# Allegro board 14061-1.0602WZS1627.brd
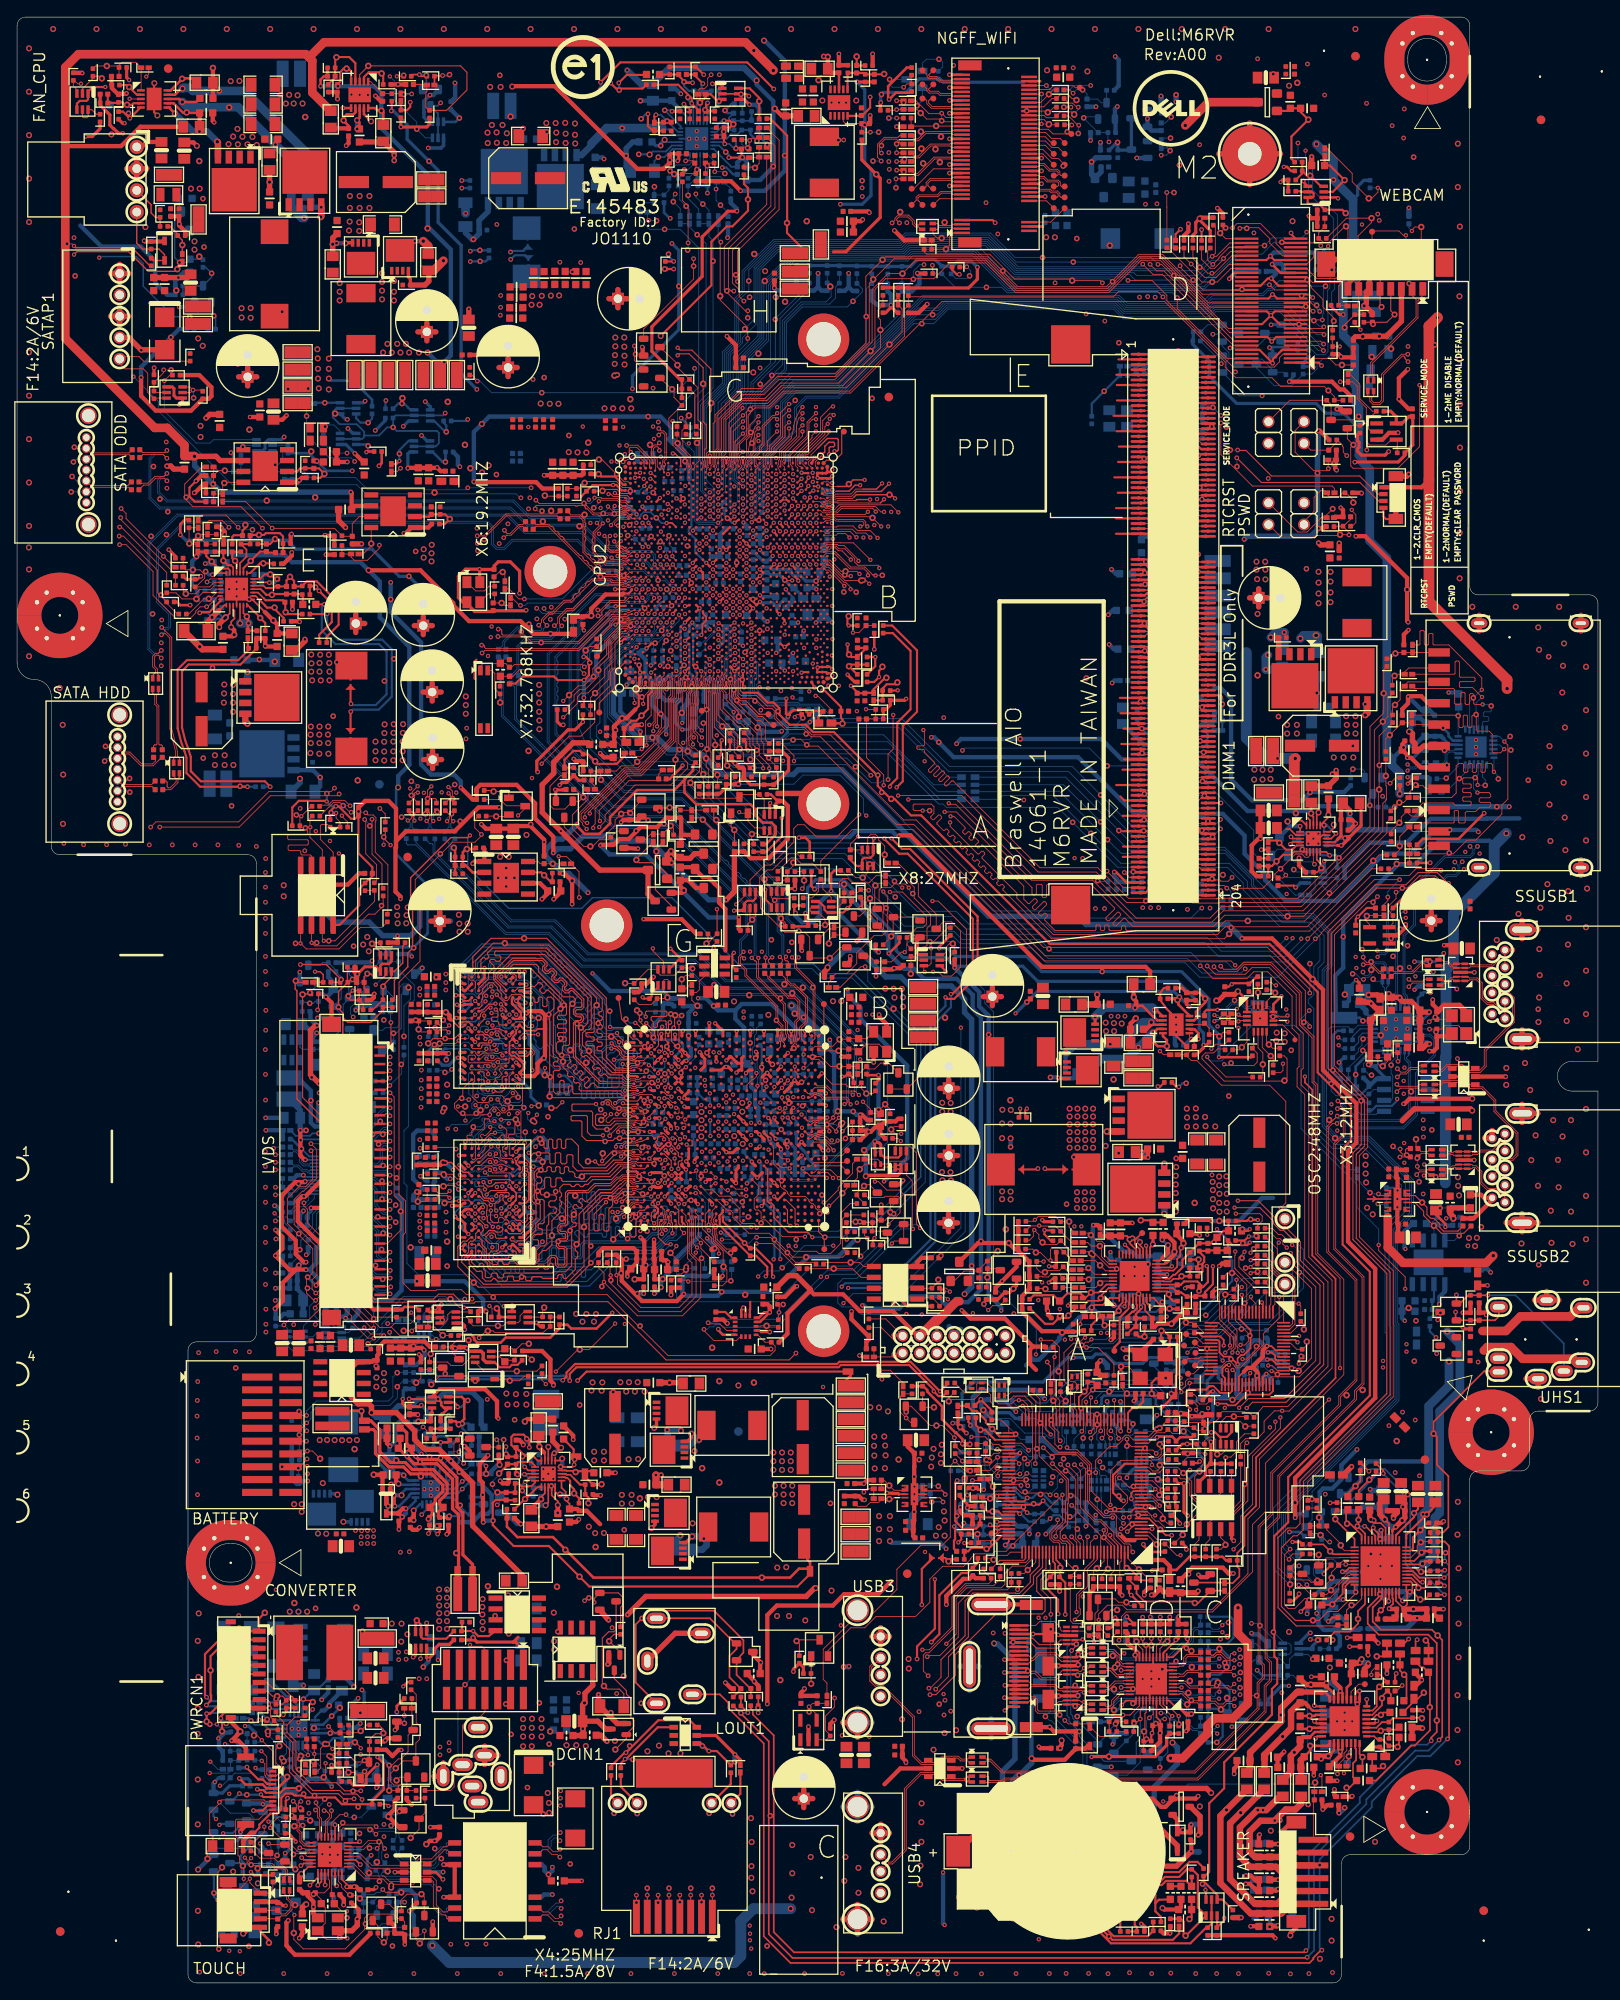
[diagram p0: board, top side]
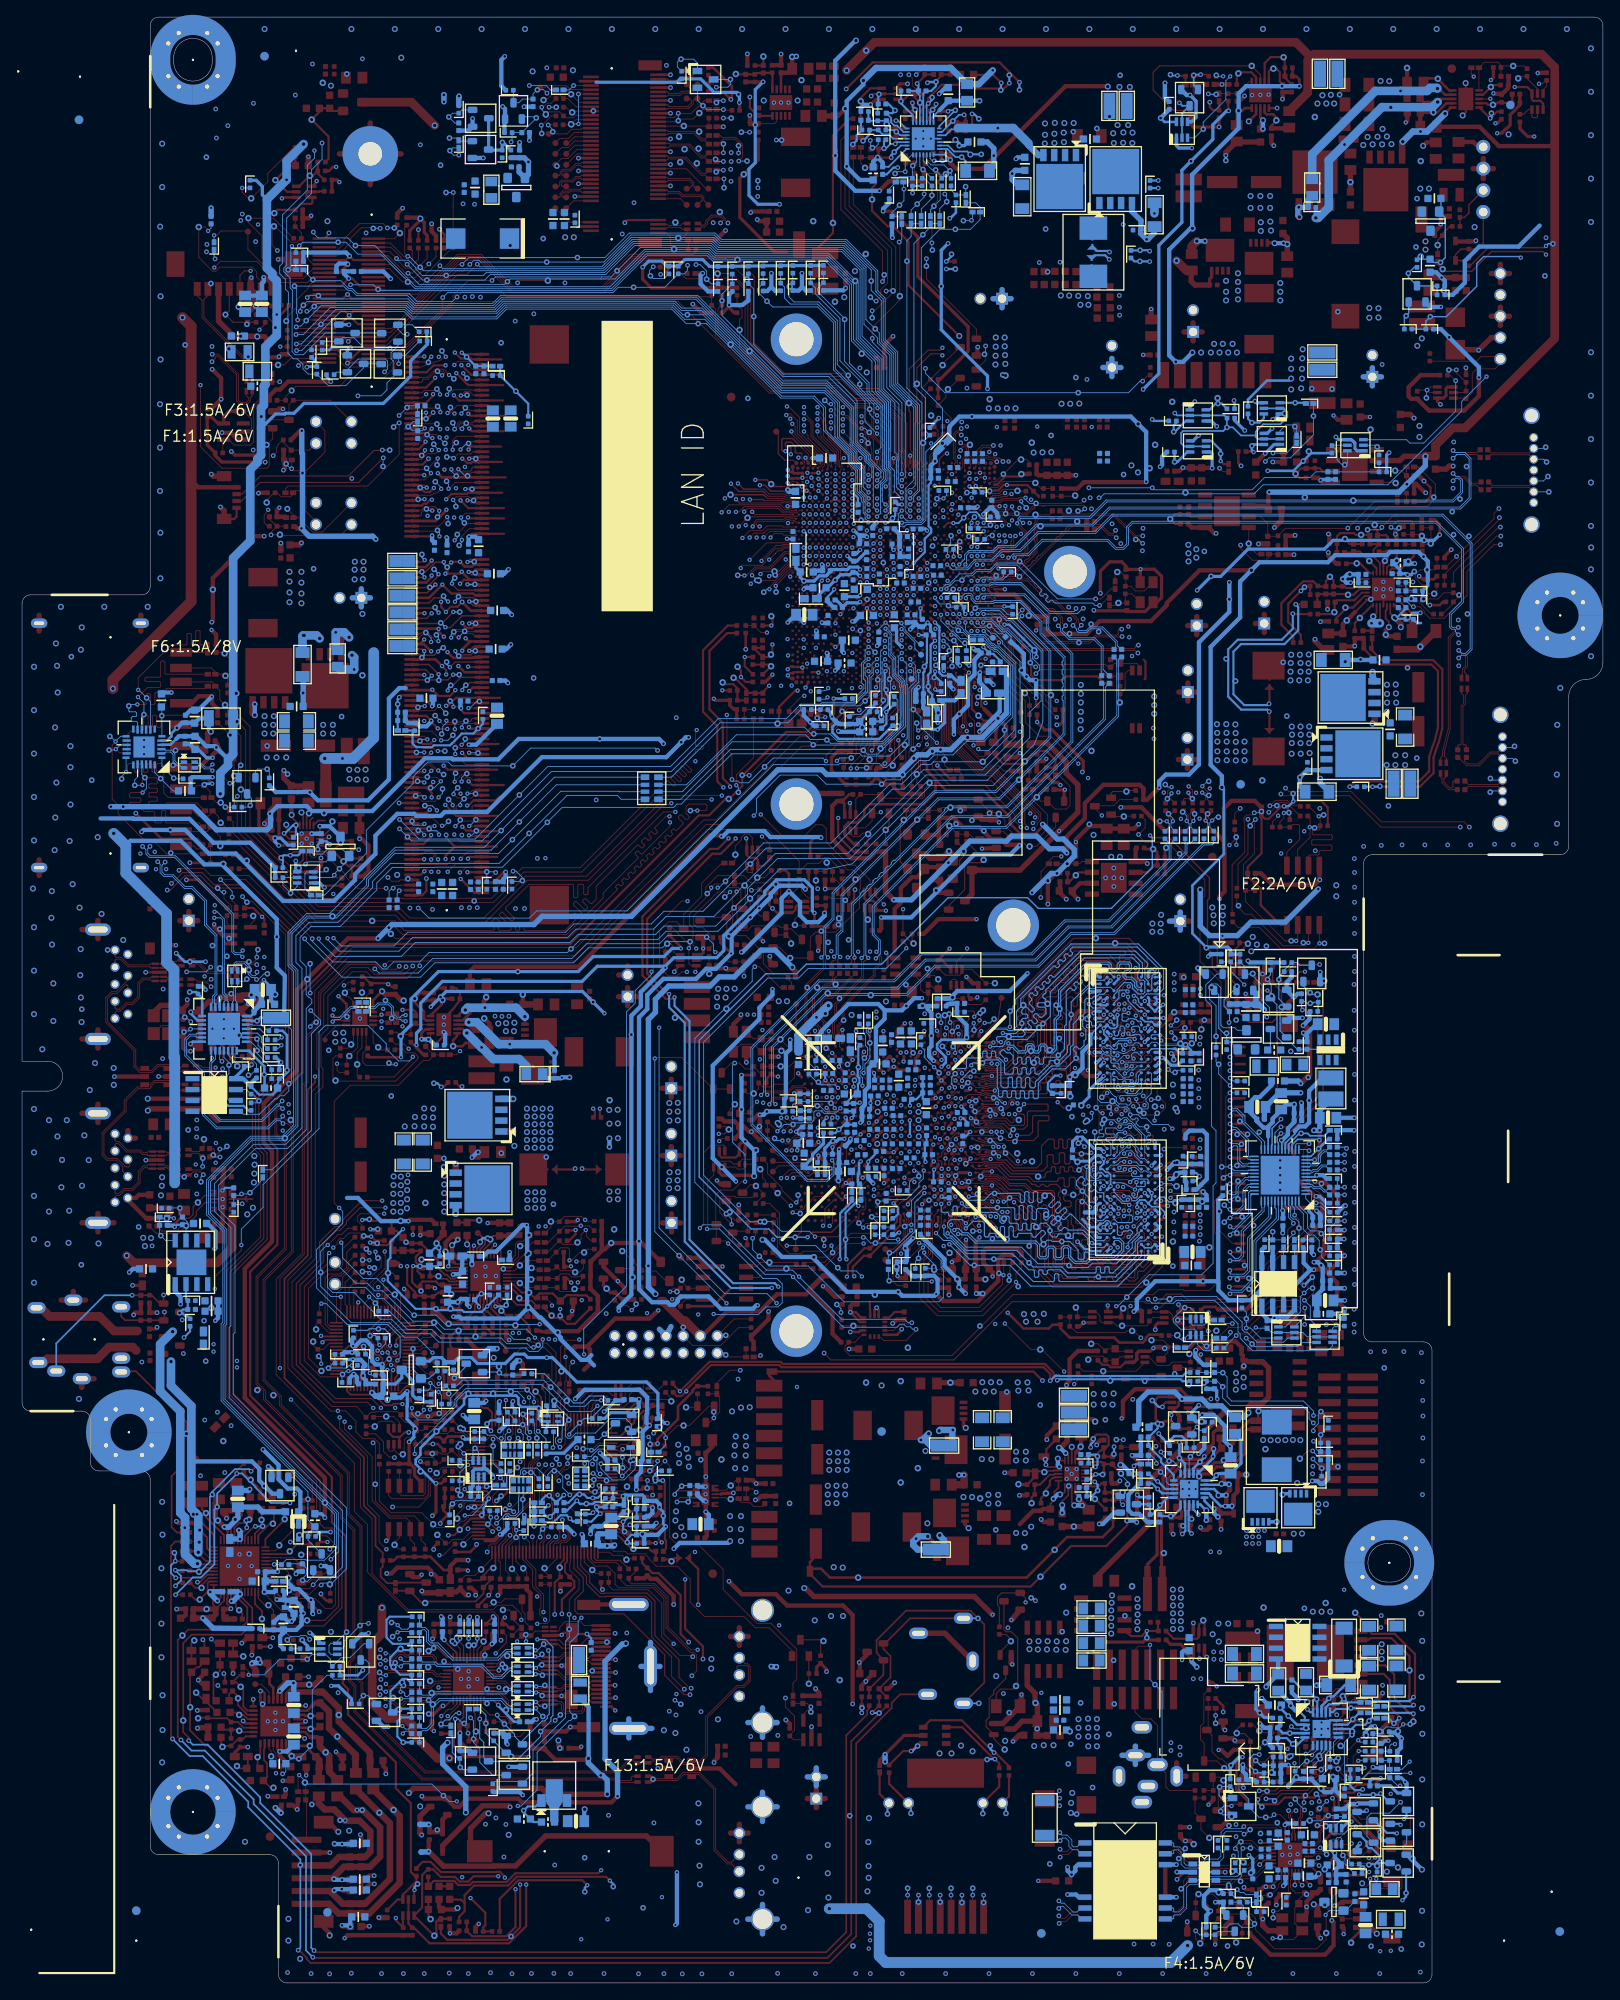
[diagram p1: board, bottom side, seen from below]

Outline 185 x 230 mm; copper layers: TOP, L2VCC, L3, L4, L5GND, BOTTOM. Coordinates in mm from the lower left corner of the outline.
Outline path: 0,229 0,154.5 arc(0.59,153.09) 2,152.5 arc(3.41,151.91) 4,150.5 4,133 arc(4.29,132.29) 5,132 27,132 arc(27.71,131.71) 28,131 28,76 arc(27.71,75.29) 27,75 21,75 arc(20.29,74.71) 20,74 20,1 arc(20.29,0.29) 21,0 154,0 arc(154.71,0.29) 155,1 155,14 arc(155.29,14.71) 156,15 169,15 arc(169.71,15.29) 170,16 170,58.9 arc(170.29,59.61) 171,59.9 176,59.9 arc(176.71,60.19) 177,60.9 177,65.9 arc(177.29,66.61) 178,66.9 184,66.9 arc(184.71,67.19) 185,67.9 185,104.34 182,104.34 arc(180.25,106.09) 182,107.84 185,107.84 185,161.4 arc(184.71,162.11) 184,162.4 171,162.4 arc(170.29,162.69) 170,163.4 170,229 arc(169.71,229.71) 169,230 1,230 arc(0.29,229.71) 0,229 ; 24.75,51.4 25.25,51.4 arc(27.5,49.15) 25.25,46.9 24.75,46.9 arc(22.5,49.15) 24.75,51.4 ; 162.75,225.25 arc(165,227.5) 167.25,225.25 167.25,224.75 arc(165,222.5) 162.75,224.75 162.75,225.25

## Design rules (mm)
constraint set DEFAULT: min track width 0.127, pair gap 0.102
net group AUDIO_IO_15: nets LINEOUT-L LINEOUT-R
net group DDR_COMP: nets DRAM_RCOMP_0 SM_RCOMP_1
net group GPU_ODT-MS: nets ODTA0 ODTA1
net group ICLK_RCOMP-MW: nets ICLKICOMP ICLKRCOMP
net group POWER_12_12: nets 1P5V_GUP_FB_M 1P5V_GUP_FB_M1
net group AGND: nets CHG_AGND
net group AUDIO_AMP_15: nets AMP_SPKR_L AMP_SPKR_R PORTC_SPK_L PORTC_SPK_L_1 PORTC_SPK_R PORTC_SPK_R_1 SPKR_IN_L SPKR_IN_R TPA3131_GAIN TPA3131_GVDD TPA3131_LINN TPA3131_LINN_1 TPA3131_MUTE TPA3131_PLIMIT TPA3131_RINN TPA3131_RINN_1
net group AUDIO_DMIC: nets AUD_DMIC_CLK AUD_DMIC_CLK_R AUD_DMIC_CLK_R_1 AUD_DMIC_DATA AUD_DMIC_DATA_R
net group AUDIO_HDA-15-MW: nets AUD_LINK_BCLK
net group AUDIO_HDA-MW: nets APU_SPKR AUD_BEEP_C AUD_BEEP_R AUD_LINK_RST_N AUD_LINK_RST_N_2 AUD_LINK_RST_N_R AUD_LINK_SDIN AUD_LINK_SDIN_1 AUD_LINK_SDO AUD_LINK_SDO_1 AUD_LINK_SDO_N AUD_LINK_SYNC AZ_BCLK_M AZ_RST_N_M AZ_SDOUT_M AZ_SYNC_M BUZZER_SPKR_R PCH_AUD_RST_N PCH_AUD_RST_N_1 SENSE_B SLEEVE_G SPKR_DET_C
net group AUDIO_IO: nets AUD_GP3 EAPD_DEPOP HPOL_CON HPOR_CON HPOUT-JD HPOUT-L HPOUT-R LINE2-VREFO LINEOUT-JD LINEOUT_C-L LINEOUT_C-R LINEOUT_CON-L LINEOUT_CON-R MIC2-L MIC2-L-1 MIC2-R MIC2-R-1 MIC2-VREFO-L MIC2-VREFO-R
net group AUDIO_IO_REF: nets JDREF MIC-CAP VRP
net group AUDIO_POP-MW: nets TPA3131_FAULT# TPA3131_SD TPA3131_SD1#
net group AUDIO_SPK_CN: nets SPKR_L+_C SPKR_L+_SNB SPKR_L-_C SPKR_L-_SNB SPKR_OUT_L+ SPKR_OUT_L- SPKR_OUT_R+ SPKR_OUT_R- SPKR_R+_C SPKR_R+_SNB SPKR_R-_C SPKR_R-_SNB TPA3131_BSNL TPA3131_BSNR TPA3131_BSPL TPA3131_BSPR
net group CARDREADER-MW: nets SD_CD_BD SD_CD_BD_CPU SD_CD_BD_IC SD_CLK_BD SD_CLK_BD_CPU SD_CLK_BD_IC SD_CMD_BD SD_CMD_BD_CPU SD_CMD_BD_IC SD_DATA0_B SD_DATA0_BD SD_DATA0_CPU SD_DATA1_B SD_DATA1_BD SD_DATA1_CPU SD_DATA2_B SD_DATA2_BD SD_DATA2_CPU SD_DATA3_B SD_DATA3_BD SD_DATA3_CPU SD_WP_BD SD_WP_BD_IC
net group CARDREADER_PWR: nets V_3_CARD_BD
net group CHARGER_4-5_MW-MW: nets AC_IN BAT_ALERT BAT_IN# BAT_IN#_1 CHG_ON# PD4405_A PD4405_K PQ4406_2 PQ4406_3 PQ4406_5 PQ4406_6 PQ4409_C PQ4409_E SYS_PRES
net group CHARGER_4_5_MW-MW: nets AC_OK#_ECIO AC_PROTECT AD_OFF_ECIO CHAR_CTL1 CHAR_CTL2 CHAR_CTL3 CHAR_ILIM_HI CHAR_ILIM_LO CHAR_ILIM_SEL CHAR_STATUS CHAR_USBOC# CHG_ON#_ECIO
net group CLOCK-MW: nets CK_25M_SIO CK_48M_SIO CK_P_33M_EC CLK_48M_SIO_C LPC_CLK0_R LPC_CLK1 LPC_CLK1_R SUSCLK_SIO_C XTAL19D2M_IN XTAL19D2M_IN_R XTAL19D2M_OUT XTAL19D2M_OUT_R
net group CONERTER_4-5_MW-MW: nets LEDC_ISET LPF RT SSTCMP SSTCMP_1 STATUS
net group CONVERTER_10_10: nets ISEN1 ISEN2 ISEN3 ISEN4 ISW OZ554_PWM RTN1 RTN2 RTN3 RTN4
net group CONVERTER_20_10: nets LDR LDR_1 OZ554_VIN VREF
net group CPU_CRITITAL-MW: nets APU_PROCHOT# APU_PROCHOT#_R IO_SMI_N LPC_PME_N PMC_BATLOW#
net group DDR3_ADDR-CMD-MW: nets M_CAS_A_N M_MAA_A0 M_MAA_A1 M_MAA_A2 M_MAA_A3 M_MAA_A4 M_MAA_A5 M_MAA_A6 M_MAA_A7 M_MAA_A8 M_MAA_A9 M_MAA_A10 M_MAA_A11 M_MAA_A12 M_MAA_A13 M_MAA_A14 M_MAA_A15 M_RAS_A_N M_SBS_A0 M_SBS_A1 M_SBS_A2 M_WE_A_N
net group DDR3_CTRL-MW: nets M_ODT_A0 M_ODT_A1 M_SCKE_A0 M_SCKE_A1 M_SCS_A_N0 M_SCS_A_N1
net group DDR3_DATA-MW: nets M_DATA_A0 M_DATA_A1 M_DATA_A2 M_DATA_A3 M_DATA_A4 M_DATA_A5 M_DATA_A6 M_DATA_A7 M_DATA_A8 M_DATA_A9 M_DATA_A10 M_DATA_A11 M_DATA_A12 M_DATA_A13 M_DATA_A14 M_DATA_A15 M_DATA_A16 M_DATA_A17 M_DATA_A18 M_DATA_A19 M_DATA_A20 M_DATA_A21 M_DATA_A22 M_DATA_A23 M_DATA_A24 M_DATA_A25 M_DATA_A26 M_DATA_A27 M_DATA_A28 M_DATA_A29 M_DATA_A30 M_DATA_A31 M_DATA_A32 M_DATA_A33 M_DATA_A34 M_DATA_A35 M_DATA_A36 M_DATA_A37 M_DATA_A38 M_DATA_A39 M_DATA_A40 M_DATA_A41 M_DATA_A42 M_DATA_A43 M_DATA_A44 M_DATA_A45 M_DATA_A46 M_DATA_A47 M_DATA_A48 M_DATA_A49 M_DATA_A50 M_DATA_A51 M_DATA_A52 M_DATA_A53 M_DATA_A54 M_DATA_A55 M_DATA_A56 M_DATA_A57 M_DATA_A58 M_DATA_A59 M_DATA_A60 M_DATA_A61 M_DATA_A62 M_DATA_A63 M_MA_DM0 M_MA_DM1 M_MA_DM2 M_MA_DM3 M_MA_DM4 M_MA_DM5 M_MA_DM6 M_MA_DM7
net group DDR3_VREF: nets DDR3_VREF_CA DDR3_VREF_CA_R DDR3_VREF_DQ DDR3_VREF_DQ_R VREF_CA_0 VREF_CA_DIMM1 VREF_DQ_0 VREF_DQ_DIMM1
net group DEEPSLEEP-MW: nets SUS_PWR_ACK_CPU
net group DISPLAY_DDC-MW: nets DDI0_DDCDATA
net group EDP_PWM: nets BKLT_ADJ CPU_LVDS_BL_ADJ CPU_LVDS_BL_ADJ_B CPU_LVDS_BL_ADJ_C DPLVDS_PWMIN DPLVDS_PWMOUT GPU_LVDS_BL_ADJ LVDS_BL_ADJ RTD_LVDS_BL_ADJ SIO_LVDS_BL_ADJ
net group FAN_PWM: nets CPU_FAN_CTRL_SIO CPU_FAN_TACH_SIO FAN_CTRL_POWER FAN_OFF_D FAN_OFF_G FAN_OFF_G2 SYS_FAN_TACH1_1 SYS_FAN_TACH1_2 SYSTEM_FAN_PWM1_1
net group FFS_4_5-MW: nets FALL_INT2 FFS_INT1 FFS_INT1_C FFS_INT2_APU FFS_INT2_C FFS_INT2_Q
net group GND-MW: nets VSS5
net group GPIO-MW: nets BATT_AMBER_LED# BATT_AMBER_LED#_C BATT_WHITE_LED# BATT_WHITE_LED#_C BIST_DISABLE BIST_DISABLE_1 BIST_EN BIST_EN_INV BIST_EN_SIO BIST_ENABLE BIST_ENABLE_1 BIST_PIN25 BOARD1 BOARD2 BOARD3 CTF_TRIP EAPD_DEPOP_1 EC_IMS EC_PSID ECIO_GP26 ECIO_GP32 ECIO_GP34 ECIO_GP63 GPIO17_THERMAL_INT GPIO19_CTF GPIO_SUS0 GPIO_SUS1 GPIO_SUS2 GPIO_SUS3 GPU_THERMAL_INT I2C0_SCL I2C1_SCL I2C2_SCL I2C4_SCL I2C5_SCL I2C6_SCL JACK_PSID LVDS_DET_A* LVDS_DET_B* LVDS_PU_5 LVDS_PU_5_1 LVDS_PU_6 LVDS_PU_24 MINI_POWER_CTRL MPCIE_DISABLE_N NFC_SCL NFC_SDA NGFF_BT_DISABLE NGFF_DETECT_PCIE NGFF_DETECT_PCIE_C NGFF_DETECT_USB NGFF_DETECT_USB_C OSD_BIST_N OSD_DN OSD_DN_R OSD_MENU OSD_MENU_R OSD_MENU_SIO OSD_UP OSD_UP_R PCB_VER_ID PCH_CHAR_CTL3 PSID_D PSID_D_1 PSID_G PW_CLEAR PW_CLEAR_H ROM_SO_C4 SEC_GPIO_SUS8 SEC_GPIO_SUS9 SEC_GPIO_SUS10 SIO_INT# SKEW1 SKEW2 SKEW3 SOC_EXTSMI_N SOC_RUNTIME_SCI# SPKR_DET WEBCAM_DET WEBCAM_DET_M
net group GPIO_RCOMP: nets GPIO_RCOMP18
net group GPU_ADDR-MS: nets MAA0 MAA1 MAA2 MAA3 MAA4 MAA5 MAA6 MAA7 MAA8 MAA9 MAA10 MAA11 MAA12 MAA13 MAA14 MAA_BA0 MAA_BA1 MAA_BA2
net group GPU_CTRL-MWS: nets CASA0# CASA1# CKEA0 CKEA1 CSA0#_0 CSA1#_0 RASA0# RASA1# WEA0# WEA1#
net group GPU_DATA-MWS: nets DQMA0 DQMA1 DQMA2 DQMA3 DQMA4 DQMA5 DQMA6 DQMA7 MDA0 MDA1 MDA2 MDA3 MDA4 MDA5 MDA6 MDA7 MDA8 MDA9 MDA10 MDA11 MDA12 MDA13 MDA14 MDA15 MDA16 MDA17 MDA18 MDA19 MDA20 MDA21 MDA22 MDA23 MDA24 MDA25 MDA26 MDA27 MDA28 MDA29 MDA30 MDA31 MDA32 MDA33 MDA34 MDA35 MDA36 MDA37 MDA38 MDA39 MDA40 MDA41 MDA42 MDA43 MDA44 MDA45 MDA46 MDA47 MDA48 MDA49 MDA50 MDA51 MDA52 MDA53 MDA54 MDA55 MDA56 MDA57 MDA58 MDA59 MDA60 MDA61 MDA62 MDA63
net group GPU_JTAG-MW: nets JTAG_TCK_VGA JTAG_TDI_VGA JTAG_TDO_VGA JTAG_TMS_VGA JTAG_TRST#_VGA
net group GPU_OTHER_4-6-MW: nets CLKTESTA CLKTESTA_C CLKTESTB CLKTESTB_C CTFB GPIO19_CTF_R GPIO_SVC GPIO_SVD GPIO_SVT GPU_CLKA0_T GPU_CLKA1_T GPU_GPIO16 GPU_HSYNC GPU_SCL GPU_SDA GPU_THERM_SHUTDOWN* GPU_VCC3_CTL_2 GPU_VCC3_CTL_3 GPU_WAKEB GPU_XO_IN GPU_XO_IN2 PCIE_CALR_RX PCIE_CALR_TX PS_0 PS_1 PS_2 PS_3 VRAM_ZQ1 VRAM_ZQ2 VRAM_ZQ3 VRAM_ZQ4
net group GPU_VREF: nets GPU_VREFG MVREFDA MVREFSA VRAM1_VREFCA VRAM1_VREFDQ VRAM2_VREFCA VRAM2_VREFDQ VRAM3_VREFCA VRAM3_VREFDQ VRAM4_VREFCA VRAM4_VREFDQ
net group HDMI_MW: nets CFG DCIN_EN DDC1L_GPU_CLK DDC1L_GPU_DATA DDCBUF DDPC_CTRL_CLK_CONN DDPC_CTRL_DATA_CONN EQ HDMI_CTRL_CLK HDMI_CTRL_DATA HDMI_GPU_CTRL_CLK HDMI_GPU_CTRL_DATA ISET PRE REXT
net group HPD-MW: nets CPU_HPD DDI0_HPD DDSP_C_HPD_CONN DP1_HPD DP_HPD DPLVDS_HPD GPU_DP_DET_CN GPU_HDMI_DET_CN HDM2_CPU_HPD HDMI2_HPD HDMI_DP2_HPD MODEL_ID_DET
net group LAN_OTHER_4-5-MW: nets LAN_RSET LANCLK_REQ_U_N RTL_ISOLATE_N RTL_ISOLATE_N_1 RTL_ISOLATE_N_2
net group LED_10_6: nets APU_SATA_LED_B APU_SATA_LED_N LAN_LEDACT_R# LINK_ACTIVITY_N LINK_PWR PB_IN_SW1 PCH_SATA_LED_1 PWR_LED_YELLOW_C PWR_LED_YELLOW_C2 SATA_LED_N_C_1 SIO_GREEN SIO_GREEN_PWM SIO_GREEN_PWM_C_1 SIO_HDD_LED SIO_HDD_LED_1 SIO_YELLOW SPEED_100*_CON SPEED_100_N SPEED_1000*_CON SPEED_1000_N SUS_LED_GREEN_C SUS_LED_GREEN_C2
net group LPC-MW: nets INIT_3V LAD0_FWH0 LAD0_FWH0_EC LAD1_FWH1 LAD1_FWH1_EC LAD2_FWH2 LAD2_FWH2_EC LAD3_FWH3 LAD3_FWH3_EC LFRAMEJ_FW4 LPC_CLKRUN# SER_IRQ
net group LPC_RCOMP: nets RCOMP_LPC_HVT
net group NGFF_CLK-MW: nets NGFF_CLKREQ0_N NGFF_CLKREQ1_N SUSCLK_NGFF
net group NGFF_OTHER-MW: nets NGFF_ALERT_N NGFF_PEWAKE0_N NGFF_POWER_CTRL_1 NGFF_POWER_CTRL_V2 NGFF_W_DISABLE1_N NGFF_W_DISABLE2_N SMB0_ALERT#_C
net group OCSILLATION-MW: nets HUB_X1 HUB_X2 LAN_XTALI LAN_XTALO PCH_RTCRST_DOWN PCH_RTCRST_PULLUP PCH_RTCX1 PCH_RTCX2 PCH_SRTCRST_DOWN PCH_SRTCRSTB_PULLUP RTCX_L XTALIN XTALOUT
net group OTHERS-MW: nets ADAPTOR_PSID_R_R APU_PROCHOT#_IO DDI0_DDCCLK DDSP_D_TX_N0 DDSP_D_TX_N2 DIMM1_SA0 DIMM1_SA1 DISCHANGE_EN EC_VCORF HDMI_HTPLG_CN1 HUB_PGANG HUB_PSELF KBRST MCLK MCSI_COMP MDAT MEM_CALRP0 MEM_MA_EVENT_L PB_IN_N_1_C PWRGD_3V_D PWRGD_3V_G PWRGD_3V_SIO RTC_INTRUDER SD_WP_BD_CPU SDMMC3_1P8_EN_R SDMMC3_PWR_EN_G SDMMC3_PWR_EN_R SDMMC_PWR_EN SDMMC_PWR_EN_G SDMMC_PWR_SEL SIO_MEM_EVENT_L SIO_MEM_EVENT_L_B SIO_MEM_EVENT_L_C SIO_PWNBTN_N SLP_S3_N_G SLP_S4_N_C SYS_PWRGD_G U1.1 U1.6 U1.24 UART1_RX UART1_TX USB_EN_1 USB_EN_2 USB_OTG_ID USB_VBUSSNS USB_VBUSSNS_R VCC_SVID_ALERT VCC_SVID_ALERT_R VCC_SVID_CLK VCC_SVID_CLK_R VCC_SVID_DATA VCC_SVID_DATA_R VGG_SVID_ALERT VGG_SVID_ALERT_R VGG_SVID_CLK VGG_SVID_CLK_R VGG_SVID_DATA VGG_SVID_DATA_R
net group PANEL_CONTROL: nets BKLT_EN BKLT_EN1 DPLVDS_BL_EN DPLVDS_PANEL_VCC LVDS_DET_B_C* PANEL_ON_1 PANEL_ON_2 PANEL_ON_3 PANEL_ON_4 PANEL_ON_5 PANEL_SEL1_CABLE PANEL_SEL1_CABLE_EC PANEL_SEL2_CABLE PANEL_SEL2_CABLE_EC PANEL_SEL3_CABLE PANEL_SEL3_CABLE_EC S_LVDS_BL_EN
net group PCIE_CLKREQ-MW: nets LDRQ# PCH_PCIECLKRQ2_N PCH_PCIECLKRQ2_N_1 PCH_PCIECLKRQ2_N_B
net group POWER: nets 3D3V_AUX_EC 3V_VA 19V_AMP_AVCC AD+_2 ADAPTOR_PSID_R AUD_DVDD AUD_REGREF AVCC33_2136 AVCC_EC CBN CBP CPVEE DPLVDS_PIN12 DPLVDS_PIN16 DVCC33_2136 EAPD_DEPOP_2 GND_AUD GPU_VCC3_CTL HUB_AVDD HUB_DVDD HUB_DVDD_R HUB_RREF HUB_VCC LED_5VSB OSD_BIST_N_1 PWRCN_DET_N PWRCN_DET_N_C SCALAR_SIO_PU SIO_AGND SIO_AVCC3 SWR_LX SWR_V12 V_3P0_BAT_VREG V_5_CODEC VBAT1 VBAT1_R VBAT2 VCC3_CARD VREF_1 VREG_PCIAUX_PCH VREG_PCIAUX_PCH_1 VSDIO
net group POWER_10_10: nets 1D8V_S0_EN 1D8V_S0_EN1 1D8V_S0_EN2 1D8V_S0_EN_G 1D8V_SPI 1D35V_S3_PWRGD 1P8V_PWR_CS 1P8V_PWR_FB 1P8V_PWR_RF 1117 ADJ 62882_COMP_R 62882_FB_VSEN 62882_NTC_R +1.5V_GPU_PG AD+_G_1 AD+_G_2 AD_IA AD_IA_HW1 AD_IA_HW2 AD_OFF BOOT1_PHASE1 PM_DPRSLPVR PRW_VGA_CORE_RBIAS PSI# PWR_1D15V_EN PWR_1D15V_FB PWR_1D15V_FB_N PWR_1P05V_CS PWR_1P05V_FB PWR_1P05V_PG_L PWR_1P05V_RF PWR_1P15V_PG_L PWR_3V_ENTRIP2 PWR_3V_FB PWR_3V_FB2 PWR_5V_BYP1 PWR_5V_ENTRIP1 PWR_5V_FB1 PWR_CHG_ACDET PWR_CHG_ILIM PWR_CHG_NC PWR_DDR4_CS PWR_DDR4_FB PWR_DDR4_TON PWR_DDR4_VDDQ PWR_DDR4_VTTREF PWR_RT8243_EMN PWR_RT8243_ENLDO PWR_RT8243_LDO3 PWR_RT8243_LDO5 PWR_RT8243_PGOOD PWR_RT8243_TON PWR_V1P5A_FB PWR_V1P8A_FB PWR_V1P24A_FB PWR_V1P24A_PG_L PWR_VCC0_COMP PWR_VCC0_COMP1 PWR_VCC0_COMP2 PWR_VCC0_CSCOMP PWR_VCC0_CSMP1 PWR_VCC0_CSP PWR_VCC0_CSREF PWR_VCC0_CSSUM PWR_VCC0_DIFFOUT PWR_VCC0_FB PWR_VCC0_ILIM PWR_VCC0_IMAX PWR_VCC0_IOUT PWR_VCC0_ROSC PWR_VCC0_TSEN PWR_VCC0_TSEN1 PWR_VGA_CORE_COMP PWR_VGA_CORE_DPRSLPVR PWR_VGA_CORE_IMON PWR_VGA_CORE_ISEN1 PWR_VGA_CORE_ISEN2 PWR_VGA_CORE_ISUM- PWR_VGA_CORE_NTC PWR_VGA_CORE_ON PWR_VGA_CORE_PGOOD PWR_VGA_CORE_PSI# PWR_VGA_CORE_RTN PWR_VGA_CORE_VSEN PWR_VGA_CORE_VW PWR_VGG_COMP PWR_VGG_COMP1 PWR_VGG_COMP2 PWR_VGG_CSCOMP PWR_VGG_CSMP1 PWR_VGG_CSREF PWR_VGG_CSSUM PWR_VGG_DIFFOUT PWR_VGG_FB PWR_VGG_ILIM PWR_VGG_IMAX PWR_VGG_ROSC PWR_VGG_TSEN PWR_VGG_TSEN1 SDMMC3_1P8_EN TSVDD VR_TT# VSUM_RC VSUM_RR
net group POWER_10_15: nets PWR_VCC0_CSN PWR_VCC0_VSN PWR_VCC0_VSP PWR_VGG_CSN PWR_VGG_CSP PWR_VGG_VBOOT/ADDR PWR_VGG_VRMP PWR_VGG_VSN PWR_VGG_VSP
net group POWER_20_10: nets PWR_0P95V_SN PWR_1D15V_SN PWR_1D15V_SVIN PWR_1P05V_BOOT_1 PWR_1P05V_SN PWR_3D3V_SN PWR_3V_BOOT2 PWR_3V_BOOT2_R PWR_5V_BOOT1 PWR_5V_BOOT1_R PWR_5V_SN PWR_DDR4_BT PWR_DDR4_BT1 PWR_DDR4_SN PWR_DDR4_VDD PWR_VCC0_BT PWR_VCC0_BTR PWR_VCC0_SN PWR_VCC0_VBOOT/ADDR PWR_VCC0_VRMP PWR_VGG_BT PWR_VGG_BTR PWR_VGG_SN
net group POWER_20_20: nets 1P8V_PWR_BOOT 1P8V_PWR_BOOT_R 1P8V_PWR_SNB PWR_0P95V_BOOT PWR_0P95V_BOOT_1 PWR_0P95V_FB PWR_VGA_CORE_BOOT1 PWR_VGA_CORE_FB PWR_VGA_CORE_FB2 PWR_VGA_CORE_SNB1 PWR_VGA_CORE_VCCP PWR_VGA_CORE_VDD PWR_VGA_CORE_VIN PX_EN TESTEN
net group POWER_40_10: nets PWR_0P95V_VCC PWR_VGG_IOUT SPV10 SPV18
net group POWER_50_10: nets 1D8V_CARD 1D8V_S5_D 1D24V_S5_D 1P05V_S5_D 1P8V_PWR_V5IN 1P15V_S5_D +3VL +5VL BQ24737_REGN DC_IN_D PWR_1P05V_VCC PWR_CHG_BTST PWR_CHG_BTST_1 PWR_CHG_CMPIN PWR_CHG_CMPIN_R PWR_CHG_CMPIN_RR PWR_CHG_VCC PWR_VCC0_PVCC PWR_VCC0_VCC PWR_VCORE_VNN_D PWR_VGG_PVCC PWR_VGG_VCC SB3V_D SB5V_D V1P8_FUSE VCCCFIOAZA_1P80 VCCCLKDDR_1P24_1P35 VCCPADCF1SI0_1P8_3P3 VCCPADCF1SI0_1P80 VCCPADCF2SI0_E_1P80 VCCPADCF3SI0_1P8_3P3 VCCRTCSUS_3P3 VCCSFRPLLDDR_1P24_1P35 VCCUSB2_1P8 VCCUSB2_3P3
net group POWER_PHASE: nets 1P8V_PWR_LGATE 1P8V_PWR_UGATE 1P8V_PWR_UGATE_R PWR_0P95V_CS PWR_0P95V_HG PWR_0P95V_HG_1 PWR_0P95V_LG PWR_0P95V_RF PWR_1P05V_BOOT PWR_1P05V_HG PWR_1P05V_HG_1 PWR_1P05V_LG PWR_3V_LGATE2 PWR_3V_UGATE2 PWR_3V_UGATE2R PWR_5V_LGATE1 PWR_5V_UGATE1 PWR_5V_UGATE1R PWR_CHG_HIDRV PWR_CHG_LODRV PWR_DDR4_LG PWR_DDR4_UG PWR_DDR4_UG1 PWR_VCC0_HG PWR_VCC0_HGR PWR_VCC0_LG PWR_VGA_CORE_LGATE1A PWR_VGA_CORE_LGATE1B PWR_VGA_CORE_UGATE1 PWR_VGG_HG PWR_VGG_HGR PWR_VGG_LG
net group PWR-EN_MW-MW: nets 1D8V_S0_EN_R CHAR_EN CHAR_EN_CPU LVDS_BL_EN_1 MLPS_EN# PWR_V1P5S_EN PWR_V1P8A_EN PWR_V1P24A_EN SB3V_EN SDCARD_PWR_EN SDMMC3_PWR_EN SLP_S0_N SLP_S3_N SLP_S4_N VCC3_EN VCC_EN VGA_1P8_EN1 VGA_1P8_EN2 VGA_1P8_EN3 VGA_1P8_EN4 VTT_EN
net group PWRGD-RST-MW: nets 1D35V_S3_PWRGD_R 1P8V_S5_PG AC_PRESENT_CPU AMD_RST# APU_PWNBTN_N APU_PWNBTN_N_R BVCCRTC_EXTPAD COREPWROK COREPWROK_XDP DDR3_DRAM_PWROK DDR3_DRAM_PWROK_D DDR3_DRAMRST_N DDR3_DRAMRST_N_A_1 DDR3_VCCA_PWRGD DDR3_VCCA_PWRGD_3P3 DDR3_VCCA_PWRGD_G DGPU_PWROK DGPU_PWROK_1D5V DRAM_RST DRAM_RST_R EXT_RST# HUB_RESET# ICH_RSMRST_N_R LAN_DISABLE_C LAN_DISABLE_N LAN_DISABLE_N_1 LAN_DISABLE_N_2 LAN_DISABLE_N_3 LAN_DISABLE_N_4 LAN_DISABLE_V3 MEM_RST OZ554_ENA PCIE_RST# PCIE_WAKE#_CPU PCIE_WAKE#_CPU_B PCIRST1# PCIRST3# PLT_RST#_CPU PLT_RST#_CPU_G PLT_RST#_D PLT_RST#_XDP PLTRST*_EC PLTRST*_SIO PLTRST_LAN_N PLTRST_N PLTRST_SL_N PM_SLP_S3#_CPU PM_SLP_S3#_CPU_D PM_SLP_S3#_CPU_G PM_SLP_S4#_CPU PM_SLP_S4#_CPU_D PM_SLP_S4#_CPU_G PMC_SUS_STAT PSTBTN_N PWR_0P95V_PG PWR_0P95V_PG_L PWR_1P05V_PG PWR_1P15V_PG PWR_V1P5S_PG PWR_V1P8A_PG PWR_V1P24A_PG PWRBTN_N PWRGD_3V PWRGD_3V_B PWRGD_3V_B_1 PWRGD_3V_C PWRGD_3V_LL PWRGD_PS_L PWRGD_PS_L1 PWRGD_PS_L2 PWRGOOD_GPU PWROK3_1 PWROK3_1_R PWROK3_2 PWROK3_2_R RSMRST*_R RSMRST_N RSMRST_N_XDP SB3V_5V_PG SB3V_5V_PG_L SIO_ATXPG SIO_GPU_EN SIO_GPU_RST SIO_PCIRSTIN# SIO_PSON_N SLP_S3_N_EC SLP_S3_N_R3 SLP_S5_N_D SLP_S5_N_EC SLP_SLP_S0#_CPU SLP_SLP_S0#_CPU_D SLP_SLP_S0#_CPU_G SUS_PWR_ACK_CPU_R SYS_PWRGD VCC0_PG VGG_PG WAKE_N WAKE_N_APU
net group SD_CARD_MW-MW: nets SDMMC1_RCOMP
net group SD_CARD_MWS-MW: nets HDD_FALL_INT2_C
net group SENSE_4_MW-MW: nets VCC0_SENSEN_CPU_N VCC0_SENSEN_CPU_P VCC0_SENSEN_N VCC0_SENSEN_P VCC1_SENSEN_CPU_N VCC1_SENSEN_CPU_P VGG_SENSEN_CPU_N VGG_SENSEN_CPU_P VGG_SENSEN_N VGG_SENSEN_P VNN_SENSEN_CPU
net group SIO_EUP: nets EC_EUP EC_EUP_EN SIO_EUP_EN# SIO_EUP_EN#_D SIO_EUP_EN#_G
net group SIO_IT8732-MW: nets A20GATE EC_HDMI_PD_N IMS PB_IN_N_1 SIO_COPEN# SIO_PWNBTN_B SW_ON_N_SIO
net group SIO_OTHERS-MW: nets AC_OK# ADAPTOR_PSID_SIO INT_SERIRQ_CPU INT_SERIRQ_OE IO_SMI_R KBCLK KDAT LDRQ#_EC LFRAMEJ_FW4_EC LPC_PME_R PD_N SFD_GPIO SIO_AMD SVID_EN SIO_DEBUG_RX SIO_DEBUG_TX SIO_INT_C SIO_K8PWR_EN SIO_PSON_D SIO_VIN1
net group SIO_REMOTE: nets DIMM_TMPIN2+ DIMM_TMPIN2- GPU_DMINUS GPU_DPLUS REMOTE1+ REMOTE1-
net group SIO_VREF: nets HM_VCCP HM_VCCP_R OCS_48M_1 OCS_48M_2 SIO_MAIN_VCC3 SIO_VCORE SIO_VIN3 SIO_VIN4 SIO_VIN5 SIO_VREF SIO_WRST# SYS_3VSB TP_SIO_VIN0 VBAT_SIO
net group SMBUS-MW: nets BATA_SCL_1 BATA_SDA_1 DPLVDS_EDIDCLK DPLVDS_EDIDCLK_C DPLVDS_EDIDSDA DPLVDS_EDIDSDA_C DPLVDS_FWCLK DPLVDS_FWSDA DPLVDS_ISPCLK DPLVDS_ISPDAT EC_SMB2_CLK EC_SMB2_DATA GPIO_VGA_03_DATA GPIO_VGA_03_DATA_R GPIO_VGA_04_CLK GPIO_VGA_04_CLK_R ISP_CLK1 ISP_DAT1 M1_SMB_CLK M1_SMB_DATA PWR_CHG_IOUT SIO_CLK_DB SIO_DAT_DB SIO_SMB2_CLK SIO_SMB2_DATA SIO_SMCLK0 SIO_SMCLK0_D SIO_SMDAT0 SIO_SMDAT0_D SMB0_ALERT# SMB0_CLK_C SMB0_CLK_MAIN SMB0_CLK_RESUME SMB0_CVT_CLK SMB0_CVT_DATA SMB0_DATA_C SMB0_DATA_MAIN SMB0_DATA_RESUME SMBUS_ISP SMBUS_ISP_G
net group SPI-MW: nets EEPROM_WP FWH_ID0 GPIO_8_ROMSO GPIO_9_ROMSI GPIO_22_ROMCS# HUB_SDA HUB_TEST/SCL ROM_CS# ROM_SI_D3 SIO_CE_N SIO_HOLD# SIO_SI SIO_SO SIO_WP# SPI_CS0_N SPI_CS0_N_ROM_1 SPI_DATAIN SPI_DATAOUT SPI_IO2 SPI_IO3 SPI_MISO_ROM_1 SPI_MOSI_1 SPI_WP# SST_HOLDJ_1
net group SPI_CLK-MW: nets GPIO_10_ROMSCK ROM_SLK_D4 SIO_SCK SIO_SCK_R SPI_CLK SPI_CLK_1
net group STRAP-MW: nets GP_CAMERASB09 GP_CAMERASB11 INT_TP# LPE_I2S2_DATAOUT_1 ME_FWP_SOC
net group SVID-MW: nets VR_SVID_ALERT# VR_SVID_CLK VR_SVID_DATA
net group TP-MW: nets AC_IN_KBC# EC_SCI JENK# RDY# SYNC TCK TDI TDO TMS TP_AD13 TP_AD14 TP_DET TP_GPU_CLKREQ# TP_NGFF_COEX1 TP_NGFF_COEX2 TP_NGFF_COEX3 TP_NGFF_LED1 TP_NGFF_LED2 TP_NGFF_MLDIR TP_Y3 XDP_PWNBTN_N
net group TRANSFORNER_20_10: nets XRF_TDC2
net group USB_HSIC_RCOMP: nets USB_HSIC_RCOMP
net group USB_OC-MW: nets USBOC01 USBOC01_H USBOC02 USBOC02_H
net group USB_RCOMP: nets USB_RCOMP
net group VRD_4_12_MW-MW: nets H_VID0 H_VID1 H_VID2 H_VID3 H_VID4 H_VID5 H_VID6 PWR_VGA_CORE_VID0 PWR_VGA_CORE_VID1 PWR_VGA_CORE_VID2 PWR_VGA_CORE_VID3 PWR_VGA_CORE_VID4 PWR_VGA_CORE_VID5 PWR_VGA_CORE_VID6 VCC0_HOT VGG_HOT
net group WLAN_CLINK_MW-MW: nets CLINK_CLK_LAN CLINK_DATA_LAN CLINK_RST_LAN_N
net group XDP-MW: nets DBG0 DBG1 DBG2 DBG3 DBG4 DBG5 DBG6 DBG7 DBG8 DBG9 DBG10 DBG11 DBG12 DBG13 DBG14 DBG15 DBG16 EDM_SOC OBSFN_C0 SOC_RUNTIME_SCI#_XDP TAP_PRDY# TAP_PREQ# TAP_PREQ#_R XDP_H_TCK XDP_H_TDI XDP_H_TDO XDP_H_TMS XDP_H_TRST_N XDP_PRESENT_N
nets with their own width: min track width 1.016; nets 3D3V_VGA_S0

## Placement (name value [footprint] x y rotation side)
AFTP1  AFTE14P-GP  [AFTE14P-75]  43.92 26.54 0 top
BAT2  ACES-CONN20G-GP  [50290-0100N-001]  32.01 64.14 270 top
BT1  BAT-AAA-BAT-034-K01-GP  [AAA-BAT-034-K01]  116.34 15.4 180 top
C3  SC10U6D3V3MX-DL-GP  [C603H36]  41.77 113.72 0 bottom
C4  SC4D7U10V3KX-DL-GP  [C603H36]  38.39 32.51 90 bottom
C5  SCD47U25V3KX-1-DL-GP  [C603H36]  32.06 23.9 90 bottom
C6  SCD1U16V2KX-3DLGP  [C402H22]  42.8 114.08 0 bottom
C7  SC1U10V2KX-1GP  [C402H22]  34.07 86.49 180 bottom
C8  SCD1U16V2KX-3DLGP  [C402H22]  156.39 191.75 180 top
C9  SC1U10V2KX-1GP  [C402H22]  31.53 86.01 90 bottom
C10  SC100P50V2JN-3DLGP  [C402H22]  36.41 35 180 bottom
C11  SC10U10V5KX-2DLGP  [C805H50]  158.9 196.45 0 bottom
C14  SCD01U50V2KX-1DLGP  [C402H22]  34.63 109.68 180 bottom
C16  SC10U10V5KX-2GP  [C805H54]  156.94 196.45 0 bottom
C20  SC4D7U25V5KX-DL-GP  [C805H54]  32.42 112.17 270 bottom
C24  SCD1U16V2KX-3DLGP  [C402H22]  135.57 203.43 0 top
C26  SCD1U16V2KX-3DLGP  [C402H22]  147.76 200.25 270 bottom
C27  SCD1U16V2KX-3DLGP  [C402H22]  163.28 183.72 0 top
C28  SCD1U16V2KX-3DLGP  [C402H22]  145.75 200.24 90 bottom
C29  SC1U10V2KX-1DLGP  [C402H22]  40.17 117.07 270 top
C30  SC1U10V2KX-1GP  [C402H22]  97.22 126.58 90 top
C31  SC1U10V2KX-1GP  [C402H22]  104.15 119.05 270 top
C32  SCD1U25V3ZY-1-LL-GP  [C603H36]  48.42 39.62 180 bottom
C33  SC27P50V2JN-2-LL-GP  [C402H22]  38.13 24.51 90 bottom
C35  SCD1U16V2KX-3DLGP  [C402H22]  156.39 189.74 180 top
C36  SC1U100V6KX-3-GP  [C1206H75]  27.36 35.66 180 bottom
C37  SC1U100V6KX-3-GP  [C1206H75]  27.36 40.31 0 bottom
C38  SC1U100V6KX-3-GP  [C1206H75]  24.16 35.69 180 bottom
C39  SC1U100V6KX-3-GP  [C1206H75]  30.92 34.85 270 bottom
C40  SC1U100V6KX-LL-GP  [C1206H71]  24.16 40.34 0 bottom
C42  SCD01U25V2KX-3GP  [C402H22]  31.3 176.35 180 bottom
C43  SCD1U25V2KX-LL-GP  [C402H22]  33.89 28.09 180 top
C44  SC150P50V2KX-1-GP  [C402H22]  32.19 176.35 0 bottom
C47  SCD1U10V2KX-5GP  [C402H22]  138.69 181.15 180 bottom
C48  SC10U25V5KX-DL-GP  [C805H58]  16.9 214.43 180 top
C49  SCD1U16V2KX-3DLGP  [C402H22]  69.58 157.2 135 bottom
C50  SC1U10V2KX-1DLGP  [C402H22]  155.61 171.53 270 top
C52  SC1U10V2KX-1DLGP  [C402H22]  153.94 179.33 90 top
C54  SCD1U16V2KX-3DLGP  [C402H22]  59.95 170.97 270 top
C56  SCD1U16V2KX-3DLGP  [C402H22]  59.95 170.08 270 top
C60  SC10U6D3V3MX-DL-GP  [C603H36]  131.58 168.09 180 bottom
C61  SCD1U16V2KX-3DLGP  [C402H22]  132.75 167.89 180 bottom
C62  SCD1U16V2KX-3DLGP  [C402H22]  90.68 159.55 0 bottom
C63  SC10U6D3V3MX-DL-GP  [C603H36]  94.48 173.75 180 bottom
C64  SC10U6D3V3MX-DL-GP  [C603H36]  129.78 164.87 270 bottom
C65  SCD1U16V2KX-3DLGP  [C402H22]  135.26 167.79 180 bottom
C66  SCD1U16V2KX-3DLGP  [C402H22]  136.74 168.07 180 bottom
C67  SC10U6D3V3MX-DL-GP  [C603H36]  129.4 160.58 270 bottom
C68  SC10U6D3V3MX-DL-GP  [C603H36]  129.58 156.06 270 bottom
C69  SCD1U16V2KX-3DLGP  [C402H22]  133.26 149.99 90 bottom
C70  SCD1U16V2KX-3DLGP  [C402H22]  129.53 152.38 270 bottom
C71  SC10U6D3V3MX-DL-GP  [C603H36]  137.68 150.32 270 bottom
C72  SC4D7U6D3V3KX-DLGP  [C603H36]  164.8 148.16 180 bottom
C73  SC4D7U6D3V3KX-DLGP  [C603H36]  162.87 144.25 90 top
C74  SCD1U16V2KX-3DLGP  [C402H22]  165.87 147.88 180 bottom
C75  SCD1U16V2KX-3DLGP  [C402H22]  162.85 145.31 90 top
C76  SC10U6D3V3MX-DL-GP  [C603H36]  91.49 154.63 270 bottom
C77  SC10U6D3V3MX-DL-GP  [C603H36]  90.92 178.41 90 bottom
C78  SCD1U16V2KX-3DLGP  [C402H22]  91.57 157.5 90 bottom
C79  SCD1U16V2KX-3DLGP  [C402H22]  94.78 169.38 0 bottom
C80  SC100P50V2JN-3GP  [C402H22]  75.52 140.87 90 top
C81  SCD1U16V2KX-3DLGP  [C402H22]  140.59 147.7 90 bottom
C82  SCD1U16V2KX-3DLGP  [C402H22]  140.6 148.67 270 bottom
C84  SC100P50V2JN-3GP  [C402H22]  99.83 74.19 270 top
C86  SCD01U25V2KX-3GP  [C402H22]  84.74 157.61 180 bottom
C87  SCD1U16V2KX-3GP  [C402H22]  38.13 25.4 90 bottom
C88  SCD1U16V2KX-3GP  [C402H22]  41.69 27.28 90 top
C89  SCD1U16V2KX-3DLGP  [C402H22]  149.49 223.77 0 top
C90  SC10U10V5KX-2GP  [C805H54]  146.13 222.91 270 top
C93  SCD1U50V3KX-DL-GP  [C603H35]  159.14 112.6 270 top
C94  SCD1U50V3KX-DL-GP  [C603H35]  157.08 115.62 0 top
C96  SCD1U50V3KX-DL-GP  [C603H35]  150.96 219.33 90 top
C97  SCD1U50V3KX-GP  [C603H36]  149 220.09 180 top
C100  SCD1U50V3KX-GP  [C603H36]  152.26 212.63 270 top
C101  SC1U25V3KX-1-DLGP  [C603H36]  160.38 109.09 180 top
C103  SCD1U16V2KX-3DLGP  [C402H22]  160.36 118.64 90 top
C104  SCD1U16V2KX-3DLGP  [C402H22]  160.36 117.75 90 top
C105  SCD1U50V3KX-DL-GP  [C603H35]  163.48 109.45 90 top
C106  SC33P50V2JN-3DLGP  [C402H22]  166.15 113.18 0 top
C107  SC33P50V2JN-3DLGP  [C402H22]  166.15 111.15 180 top
C109  SC10U6D3V3MX-DL-GP  [C603H36]  17.26 198.76 180 top
C110  SC1U25V3KX-1-DLGP  [C603H36]  15.99 198.76 180 top
C111  SCD1U16V2KX-3GP  [C402H22]  152.59 206.47 90 top
C112  SC10U10V5KX-2DLGP  [C805H50]  20.3 198.93 180 top
C114  SCD01U50V2KX-1DLGP  [C402H22]  13.82 174.7 270 top
C115  SCD01U50V2KX-1DLGP  [C402H22]  13.82 175.62 270 top
C116  SCD1U16V2KX-3DLGP  [C402H22]  41.13 129.81 90 top
C118  SCD01U50V2KX-1DLGP  [C402H22]  13.91 178.47 270 top
C119  SCD01U50V2KX-1DLGP  [C402H22]  13.91 179.38 270 top
C121  SC100P50V2JN-3GP  [C402H22]  158.6 194.74 0 top
C126  SC22P50V2JN-4GP  [C402H22]  154.21 48.87 90 top
C127  SC10U6D3V3MX-DL-GP  [C603H36]  157.31 47.02 90 bottom
C129  SC10U6D3V3MX-DL-GP  [C603H36]  151.93 44.22 90 top
C130  SCD1U25V2KX-GP  [C402H22]  152.81 53.47 90 top
C131  SCD1U16V2KX-3DLGP  [C402H22]  156.98 48.11 90 bottom
C132  SC100P50V2JN-3GP  [C402H22]  154.57 42.32 0 top
C134  SC100P50V2JN-3DLGP  [C402H22]  171.1 77.98 180 top
C138  SC4D7U6D3V3KX-DLGP  [C603H36]  155.74 56.13 180 top
C139  SC4D7U6D3V3KX-DLGP  [C603H36]  157.01 56.13 180 top
C140  SC2D2U10V3KX-1DLGP-U  [C603H36]  158.29 56.07 180 top
C141  SCD01U50V2KX-1DLGP  [C402H22]  16.6 139.61 270 top
C142  SCD01U50V2KX-1DLGP  [C402H22]  16.6 140.62 270 top
C144  SC10U10V5KX-2DLGP  [C805H50]  159.93 57.53 180 top
C145  SCD1U16V2KX-3DLGP  [C402H22]  159.93 55.24 270 top
C146  SC10U10V5KX-2DLGP  [C805H50]  161.96 57.53 180 top
C147  SCD1U16V2KX-3DLGP  [C402H22]  161.96 55.24 90 top
C149  SCD01U50V2KX-1DLGP  [C402H22]  16.99 143.84 0 top
C150  SC1U10V2KX-1DLGP  [C402H22]  161.07 45.77 90 bottom
C151  SCD01U50V2KX-1DLGP  [C402H22]  15.97 143.84 0 top
C154  SC10U10V5KX-2DLGP  [C805H50]  165.97 57.2 0 top
C155  SC10U10V5KX-2DLGP  [C805H50]  163.94 57.2 0 top
C157  SC100P50V2JN-3DLGP  [C402H22]  170.09 76.07 180 top
C159  SC100P50V2JN-3DLGP  [C402H22]  171.1 80.01 0 top
C160  SC100P50V2JN-3DLGP  [C402H22]  170.04 73.25 0 top
C163  SCD1U16V2KX-3DLGP  [C402H22]  48.04 108.33 0 top
C170  SC1U10V2KX-1GP  [C402H22]  152.2 48.59 180 bottom
C174  SCD1U16V2ZY-2GP  [C402H22]  132.04 57.89 90 bottom
C175  SCD1U16V2ZY-2GP  [C402H22]  137.09 60.81 90 top
C176  SC100P50V2JN-3DLGP  [C402H22]  140.22 66.47 270 top
C179  SCD1U16V2KX-3DLGP  [C402H22]  134.45 48.31 270 top
C180  SCD1U16V2ZY-2GP  [C402H22]  130.56 46.28 270 top
C181  SC2D2U6D3V2MX-GP  [C402H22]  129.19 66.27 180 bottom
C182  SCD1U16V2KX-3DLGP  [C402H22]  131.33 68.96 270 top
C183  SCD1U16V2KX-3DLGP  [C402H22]  114.1 68.24 90 bottom
C185  SCD1U16V2KX-3DLGP  [C402H22]  133.43 75.31 270 top
C186  SCD1U16V2KX-3DLGP  [C402H22]  48.49 99.69 270 top
C189  SC1U25V3KX-1-DLGP  [C603H36]  126.39 70.69 180 top
C190  SC4D7U6D3V3KX-GP  [C603H36]  34.53 17.32 270 bottom
C191  SCD1U16V2KX-3GP  [C402H22]  34.42 16.31 270 bottom
C192  SC1U25V3KX-1-DLGP  [C603H36]  162.48 29.92 270 top
C193  SC1U25V3KX-1-DLGP  [C603H36]  162.48 28.73 270 top
C194  SC4D7U6D3V3KX-GP  [C603H36]  31.5 13.79 90 bottom
C195  SCD1U25V3KX-GP  [C603H36]  34.93 14.02 270 bottom
C198  SCD027U50V3KX-DL-GP  [C603H36]  157.94 25.1 270 top
C199  SCD027U50V3KX-DL-GP  [C603H36]  161.53 33.02 270 top
C200  SCD027U50V3KX-DL-GP  [C603H36]  161.42 31.65 270 top
C201  SCD1U16V2KX-3DLGP  [C402H22]  32.42 19.81 180 top
C202  SCD1U16V2KX-3DLGP  [C402H22]  33.05 11.38 180 top
C203  SC100P50V2JN-3DLGP  [C402H22]  160.82 34.16 270 top
C204  SCD1U16V2KX-3DLGP  [C402H22]  33.31 19.81 180 top
C205  SC15P50V2JN-DL-GP  [C402H22]  34.45 10.54 270 top
C207  SC1U10V2KX-1GP  [C402H22]  31.2 19.91 0 bottom
C208  SC1U25V3KX-1-DLGP  [C603H36]  156.9 36.17 90 top
C210  SCD027U50V3KX-DL-GP  [C603H36]  157.51 23.67 270 top
C211  SCD1U16V2KX-3DLGP  [C402H22]  120.01 54.44 0 bottom
C212  SC15P50V2JN-DL-GP  [C402H22]  37.33 10.33 90 top
C213  SCD1U16V2KX-3GP  [C402H22]  24.49 24 90 bottom
C214  SC1U10V2KX-1DLGP  [C402H22]  117.51 52.98 0 bottom
C215  SC22U6D3V5MX-2DLGP  [C805H54]  116.06 53.47 0 bottom
C216  SC22U6D3V5MX-2DLGP  [C805H54]  132.09 66.9 0 bottom
C217  SCD1U16V2KX-3DLGP  [C402H22]  135.11 66.75 90 top
C218  SC1U10V2KX-1DLGP  [C402H22]  111.65 67.56 90 top
C220  SC4D7U6D3V3KX-GP  [C603H36]  39.07 12.93 0 bottom
C221  SC4D7U6D3V3KX-GP  [C603H36]  38.01 16.76 180 bottom
C222  SCD01U50V3KX-4GP  [C603H36]  145.65 7.72 90 bottom
C223  SCD22U25V3KX-DL-GP  [C603H36]  151.39 26.47 270 top
C224  SCD22U25V3KX-DL-GP  [C603H36]  150.15 34.8 0 top
C225  SCD68U16V3KX-GP-U  [C603H36]  143.52 26.01 270 top
C226  SC1000P50V3JN-DLGP  [C603H36]  145.32 7.37 0 top
C227  SCD1U16V2KX-3DLGP  [C402H22]  25.97 27.56 180 bottom
C228  SCD22U25V3KX-DL-GP  [C603H36]  150.15 32 180 top
C229  SCD22U25V3KX-DL-GP  [C603H36]  150.15 29.21 0 top
C231  SCD1U16V2KX-3DLGP  [C402H22]  122.03 55.27 90 bottom
C232  SC2D2U10V3KX-1DLGP-U  [C603H36]  33.38 7.32 0 top
C234  SC10U10V5KX-2GP  [C805H54]  97.06 26.67 0 top
C235  SCD68U16V3KX-GP-U  [C603H36]  146.74 26.42 90 top
C236  SC1000P50V3JN-DLGP  [C603H36]  145.32 10.03 180 top
C238  SCD1U16V2KX-3GP  [C402H22]  103.16 26.67 90 top
C239  SCD01U50V3KX-4GP  [C603H36]  145.47 10.87 90 bottom
C243  SCD01U50V3KX-4GP  [C603H36]  145.47 16.33 90 bottom
C247  SCD68U16V3KX-GP-U  [C603H36]  150.99 25.22 90 top
C248  SC1000P50V3JN-DLGP  [C603H36]  145.32 15.49 180 top
C249  SCD1U16V2KX-3GP  [C402H22]  93.63 33.15 180 top
C251  SC1U10V2KX-1DLGP  [C402H22]  91.73 33.15 180 top
C255  SCD68U16V3KX-GP-U  [C603H36]  148.29 25.22 270 top
C256  SC1000P50V3JN-DLGP  [C603H36]  145.32 12.83 0 top
C263  SCD01U50V3KX-4GP  [C603H36]  145.47 12.14 90 bottom
C267  SC100P50V2JN-3DLGP  [C402H22]  86.32 34.44 270 top
C268  SC100P50V2JN-3DLGP  [C402H22]  84.26 34.42 90 top
C270  SCD1U16V2KX-3DLGP  [C402H22]  154.21 20.8 270 top
C271  SCD1U16V2KX-3DLGP  [C402H22]  103.16 27.69 90 top
C272  SC10U10V5KX-2GP  [C805H54]  99.09 26.67 0 top
C283  SC10U10V5KX-2DLGP  [C805H50]  40.44 102.49 270 bottom
C284  SCD1U16V2KX-3DLGP  [C402H22]  40.06 101.07 90 bottom
C289  SCD1U16V2KX-3DLGP  [C402H22]  35.69 100.89 90 bottom
C290  SCD1U16V2KX-3DLGP  [C402H22]  35.69 101.77 90 bottom
C291  SC22U6D3V5MX-2DLGP  [C805H54]  37.65 103.15 0 bottom
C292  SC10U10V5KX-2DLGP  [C805H50]  32.51 79.85 270 bottom
C293  SCD1U16V2KX-3DLGP  [C402H22]  32.34 81.27 270 bottom
C295  SCD1U16V2KX-3DLGP  [C402H22]  37.45 89.03 180 bottom
C296  SC10U10V5KX-2DLGP  [C805H50]  32.16 101.22 270 bottom
C297  SCD1U16V2KX-3DLGP  [C402H22]  33.51 88.62 90 bottom
C298  SCD1U16V2KX-3DLGP  [C402H22]  32.34 82.16 90 bottom
C299  SCD1U16V2KX-3DLGP  [C402H22]  33.51 89.56 90 bottom
C300  SCD1U16V2KX-3DLGP  [C402H22]  31.53 95.12 270 bottom
C301  SCD1U16V2KX-3DLGP  [C402H22]  31.53 96.01 270 bottom
C302  SCD1U16V2KX-3DLGP  [C402H22]  131.91 188.72 180 bottom
C303  SCD1U16V2KX-3DLGP  [C402H22]  130.94 188.72 0 bottom
C304  SC22U6D3V3MX-1-DL-GP  [C603H40]  60.46 199.48 180 top
C305  SC22U6D3V3MX-1-DL-GP  [C603H40]  58.45 198.43 270 top
C313  SC47P50V2JN-3GP  [C402H22]  83.19 206.25 180 bottom
C314  SCD1U16V2KX-3DLGP  [C402H22]  141.33 116.1 180 top
C315  SCD1U16V2KX-3DLGP  [C402H22]  63.99 172.24 270 top
C316  SCD1U16V2KX-3DLGP  [C402H22]  63.99 171.3 270 top
C322  SCD1U16V2KX-3DLGP  [C402H22]  57.77 152.5 180 bottom
C324  SCD1U16V2KX-3DLGP  [C402H22]  56.32 155.57 180 bottom
C325  SCD1U16V2KX-3DLGP  [C402H22]  58.66 152.5 180 bottom
C328  SCD1U16V2KX-3DLGP  [C402H22]  57.21 155.57 180 bottom
C364  SCD1U16V2KX-3DLGP  [C402H22]  122.04 224.07 90 top
C372  SCD1U16V2KX-3DLGP  [C402H22]  98.31 150.44 180 top
C380  SCD1U16V2KX-3GP  [C402H22]  97.51 132.12 180 top
C385  SCD1U16V2KX-3GP  [C402H22]  99.21 150.45 0 top
C391  SC2D2U10V3KX-1DLGP-U  [C603H36]  121.52 206.38 0 bottom
C393  SCD1U16V3KX-3GP  [C603H36]  156.22 114.5 90 bottom
C397  SCD1U50V3KX-DL-GP  [C603H35]  160.82 114.55 180 top
C398  SCD1U16V2KX-3DLGP  [C402H22]  128.68 128.4 0 bottom
C399  SCD1U16V2KX-3GP  [C402H22]  129.6 128.4 180 bottom
C400  SCD1U50V3KX-DL-GP  [C603H35]  163.48 110.67 90 top
C401  SC1U25V3KX-1-DLGP  [C603H36]  163.41 113.82 270 top
C402  SC1U25V3KX-1-DLGP  [C603H36]  163.41 112.62 270 top
C403  SC1U10V2KX-1DLGP  [C402H22]  138.59 128.12 180 bottom
C404  SC1U10V2KX-1DLGP  [C402H22]  136.93 128.12 180 bottom
C405  SC10U6D3V3MX-DL-GP  [C603H36]  135.88 127.99 0 bottom
C406  SC10U6D3V3MX-DL-GP  [C603H36]  134.61 127.99 0 bottom
C407  SC1U10V2KX-1DLGP  [C402H22]  132.52 128.37 180 bottom
C408  SC1U10V2KX-1DLGP  [C402H22]  131.61 128.37 180 bottom
C409  SCD1U16V2KX-3DLGP  [C402H22]  170.03 126.11 180 top
C450  SC10U10V5KX-2DLGP  [C805H50]  159.75 56.64 180 bottom
C474  SCD1U16V2KX-3DLGP  [C402H22]  154.31 44.37 180 bottom
C478  SC10U6D3V3MX-DL-GP  [C603H36]  153.17 43.99 0 bottom
C483  SCD1U16V2KX-3DLGP  [C402H22]  165.41 43.76 90 top
C485  SC10U6D3V3MX-DL-GP  [C603H36]  165.69 42.67 270 top
C486  SCD1U16V2KX-3DLGP  [C402H22]  48.42 116.2 90 bottom
C489  SCD1U16V2KX-3DLGP  [C402H22]  48.42 90.68 270 top
C493  SC10U6D3V3MX-GP  [C603H38]  162.01 42.7 270 top
C495  SCD1U16V2KX-3DLGP  [C402H22]  161.88 43.74 270 top
C500  SCD1U16V2KX-3DLGP  [C402H22]  48.42 116.59 270 top
C509  SC10U6D3V3MX-GP  [C603H38]  154.41 42.06 0 bottom
C514  SCD1U16V2KX-3DLGP  [C402H22]  48.42 115.57 270 top
C516  SCD1U16V2KX-3GP  [C402H22]  155.53 41.76 0 bottom
C521  SC1U16V3KX-2GP  [C603H36]  154.9 25.65 270 bottom
C522  SCD1U16V2KX-3DLGP  [C402H22]  87.27 132.8 0 top
C523  SCD1U16V2KX-3DLGP  [C402H22]  89.06 138.72 180 top
C524  SC2200P50V2KX-2DLGP  [C402H22]  122.03 56.18 270 bottom
C525  SCD1U16V2KX-3DLGP  [C402H22]  110.4 50.5 90 top
C527  SCD1U16V2KX-3DLGP  [C402H22]  112.63 52.43 270 bottom
C528  SCD1U16V2KX-3DLGP  [C402H22]  112.63 55.47 270 bottom
C529  SCD1U16V2KX-3DLGP  [C402H22]  112.25 53.7 90 top
C530  SCD1U16V2KX-3DLGP  [C402H22]  116.06 61.16 90 bottom
C531  SC1KP50V2KX-1GP  [C402H22]  157.61 39.34 90 top
C534  SCD1U16V2KX-3DLGP  [C402H22]  39.05 17.09 0 bottom
C535  SC1U10V2KX-1DLGP  [C402H22]  116.31 55.7 90 bottom
C536  SCD1U16V2KX-3DLGP  [C402H22]  38.03 12.78 180 bottom
C537  SCD1U16V2KX-3DLGP  [C402H22]  40.98 12.62 180 bottom
C538  SCD1U16V2KX-3DLGP  [C402H22]  34.42 15.42 90 bottom
C540  SC2D2U10V3KX-1DLGP-U  [C603H36]  27.99 9.9 180 bottom
C542  SCD1U16V2KX-3DLGP  [C402H22]  25.94 25.6 0 bottom
C543  SC10U25V5KX-DL-GP  [C805H58]  153.2 32.51 180 bottom
C544  SCD1U16V2KX-3DLGP  [C402H22]  39.56 15.65 270 bottom
C545  SCD1U50V3KX-DL-GP  [C603H35]  153.4 35.81 270 top
C547  SCD1U16V2KX-3DLGP  [C402H22]  39.56 14.76 270 bottom
C548  SCD1U16V2KX-3DLGP  [C402H22]  37.14 12.78 180 bottom
C549  SCD1U16V2KX-3DLGP  [C402H22]  27.36 29.16 90 bottom
C551  SC10U25V5KX-DL-GP  [C805H58]  153.2 28.83 180 bottom
C552  SCD1U50V3KX-DL-GP  [C603H35]  153.55 24.54 0 top
C554  SCD1U16V2KX-3DLGP  [C402H22]  40.6 10.89 270 top
C557  SCD1U16V2KX-3DLGP  [C402H22]  48.42 114.43 90 bottom
C558  SC1U10V2KX-1GP  [C402H22]  43.98 9.45 270 bottom
C559  SC1U10V2KX-1GP  [C402H22]  45.35 6.05 0 top
C561  SC1U10V2KX-1GP  [C402H22]  43.75 5.82 90 top
C562  SCD1U16V2KX-3DLGP  [C402H22]  30.06 12.24 180 bottom
C568  SC1U10V2KX-1DLGP  [C402H22]  11.49 223.06 270 top
C571  SCD1U10V2MX-3DLGP  [C402H22]  127.4 70.62 180 top
C572  SCD1U16V2KX-3GP  [C402H22]  98.35 156.65 180 top
C573  SCD1U16V2KX-3DLGP  [C402H22]  99.32 156.64 0 top
C574  SCD1U16V2KX-3GP  [C402H22]  98.95 147.88 90 top
C575  SCD1U16V2KX-3GP  [C402H22]  99.35 159.26 0 top
C576  SCD1U16V2KX-3GP  [C402H22]  138.29 184.53 270 bottom
C582  SC22U6D3V3MX-1-DL-GP  [C603H40]  58.41 194.78 270 top
C583  SC22U6D3V3MX-1-DL-GP  [C603H40]  58.41 195.99 270 top
C590  SC22U6D3V3MX-1-DL-GP  [C603H40]  86.85 163.05 270 bottom
C591  SC22U6D3V3MX-1-DL-GP  [C603H40]  82.93 159.31 180 bottom
C592  SC22U6D3V3MX-1-DL-GP  [C603H40]  86.14 159.99 270 bottom
C597  SC1U10V2KX-1DLGP  [C402H22]  82.2 163.79 270 bottom
C598  SC1U10V2KX-1DLGP  [C402H22]  81.41 159.62 180 bottom
C599  SC1U10V2KX-1DLGP  [C402H22]  80.52 159.62 180 bottom
C600  SC1U10V2KX-1DLGP  [C402H22]  80.53 161.57 90 bottom
C605  SC1U10V2KX-1DLGP  [C402H22]  81.84 169.23 270 bottom
C606  SC1U10V2KX-1DLGP  [C402H22]  81.25 167.33 180 bottom
C607  SC1U10V2KX-1DLGP  [C402H22]  80.28 170.11 90 bottom
C608  SC1U10V2KX-1DLGP  [C402H22]  68.86 182.35 0 top
C609  SC1U10V2KX-1DLGP  [C402H22]  69.97 182.35 0 top
C612  SC1U10V2KX-1DLGP  [C402H22]  79.65 159.1 180 bottom
C614  SC1U10V2KX-1DLGP  [C402H22]  87.66 166.79 180 bottom
C616  SCD1U16V2KX-3DLGP  [C402H22]  48.42 88.9 270 top
C617  SC1U10V2KX-1DLGP  [C402H22]  72.32 155.6 90 bottom
C618  SC1U10V2KX-1DLGP  [C402H22]  77.88 164.7 90 bottom
C619  SC1U10V2KX-1DLGP  [C402H22]  80.28 164.56 270 bottom
C620  SC1U10V2KX-1DLGP  [C402H22]  80.27 163.17 270 bottom
C621  SC1U10V2KX-1DLGP  [C402H22]  58 182.47 0 top
C622  SC1U10V2KX-1DLGP  [C402H22]  58.92 182.47 0 top
C623  SC1U10V2KX-1DLGP  [C402H22]  60.67 182.47 0 top
C624  SC1U10V2KX-1DLGP  [C402H22]  61.61 182.47 0 top
C625  SC1U10V2KX-1DLGP  [C402H22]  86.16 166.95 0 bottom
C626  SC1U10V2KX-1DLGP  [C402H22]  86.14 165.02 180 bottom
C627  SC1U10V2KX-1DLGP  [C402H22]  87.16 172.51 0 bottom
C629  SC1U10V2KX-1DLGP  [C402H22]  86.93 169.77 180 bottom
C630  SC1U10V2KX-1DLGP  [C402H22]  84.56 190.11 270 top
C631  SC1U10V2KX-1DLGP  [C402H22]  84.56 188.99 270 top
C632  SC1U10V2KX-1DLGP  [C402H22]  90.31 161.81 270 bottom
C633  SC1U10V2KX-1DLGP  [C402H22]  89.44 160.94 270 bottom
C634  SC1U10V2KX-1DLGP  [C402H22]  88.63 199.59 0 top
C641  SC22U6D3V5MX-2DLGP  [C805H54]  129.42 148.26 180 bottom
C642  SC22U6D3V5MX-2DLGP  [C805H54]  93.45 160.07 270 bottom
C643  SC22U6D3V5MX-2DLGP  [C805H54]  129.9 183.03 0 bottom
C644  SC22U6D3V5MX-2DLGP  [C805H54]  127.82 183.03 0 bottom
C711  SC10P50V2JN-4GP  [C402H22]  30.5 8.94 180 top
C714  SCD1U16V2KX-3DLGP  [C402H22]  123.88 27.84 0 top
C721  SCD1U16V2KX-3DLGP  [C402H22]  118.4 39.37 180 bottom
C752  SC47P50V2JN-3GP  [C402H22]  97.34 106.79 0 top
C753  SCD1U10V2KX-5GP  [C402H22]  107.42 84.84 270 top
C755  SCD01U50V2KX-1DLGP  [C402H22]  101.13 89.69 0 top
C756  SC12P50V2JN-DL-GP  [C402H22]  97.34 108.82 0 top
C757  SC12P50V2JN-DL-GP  [C402H22]  97.34 110.85 180 top
C758  SC1U10V2KX-1DLGP  [C402H22]  87.56 99.97 180 bottom
C759  SC1U10V2KX-1DLGP  [C402H22]  88.48 99.97 180 bottom
C760  SC1U10V2KX-1DLGP  [C402H22]  79.46 114.25 270 bottom
C761  SC1U10V2KX-1DLGP  [C402H22]  75.15 114.6 90 bottom
C762  SC120P50V2JN-1-DL-GP  [C402H22]  83.11 87.99 180 bottom
C763  SCD1U16V2KX-3GP  [C402H22]  83.62 83.93 180 bottom
C764  SCD1U16V2KX-3GP  [C402H22]  77.15 83.93 0 top
C765  SC1U10V2KX-1DLGP  [C402H22]  79.15 105.03 270 bottom
C766  SC1U10V2KX-1DLGP  [C402H22]  79.15 105.92 270 bottom
C767  SC1U10V2KX-1DLGP  [C402H22]  74.91 98.64 0 bottom
C768  SC1U10V2KX-1DLGP  [C402H22]  79.15 104.14 270 bottom
C769  SC1U10V2KX-1DLGP  [C402H22]  76.51 92.31 180 bottom
C770  SC1U10V2KX-1DLGP  [C402H22]  75.11 101.83 90 bottom
C771  SC4D7U6D3V3KX-DLGP  [C603H36]  48.17 83.95 90 bottom
C772  SC22U6D3V5MX-2DLGP  [C805H54]  48.03 85.52 90 bottom
C773  SC1U10V2KX-1DLGP  [C402H22]  74.87 100.47 90 bottom
C774  SCD1U16V2KX-3DLGP  [C402H22]  78.9 96.9 270 bottom
C775  SC1U10V2KX-1DLGP  [C402H22]  77.88 93.73 270 bottom
C776  SC1U10V2KX-1DLGP  [C402H22]  62.07 97.02 0 bottom
C777  SC1U10V2KX-1DLGP  [C402H22]  61.52 102.72 90 bottom
C778  SC1U10V2KX-1DLGP  [C402H22]  48.44 87.38 90 bottom
C779  SC1U10V2KX-1DLGP  [C402H22]  87.68 102.45 180 bottom
C780  SC4D7U6D3V3KX-DLGP  [C603H36]  88.02 104 270 bottom
C781  SCD1U16V2KX-3DLGP  [C402H22]  88.57 102.45 180 bottom
C782  SC1U10V2KX-1DLGP  [C402H22]  86.26 102.23 90 bottom
C783  SC1U10V2KX-1DLGP  [C402H22]  86.26 101.36 90 bottom
C784  SC4D7U6D3V3KX-DLGP  [C603H36]  84.66 107.52 90 bottom
C785  SC1U10V2KX-1DLGP  [C402H22]  72.95 85.58 270 top
C786  SC1U10V2KX-1DLGP  [C402H22]  79.41 88.65 270 bottom
C787  SC4D7U6D3V3KX-DLGP  [C603H36]  72.57 83.55 270 top
C788  SC4D7U6D3V3KX-DLGP  [C603H36]  75.36 83.47 90 top
C789  SCD1U16V2KX-3DLGP  [C402H22]  72.95 84.69 270 top
C790  SCD1U16V2KX-3DLGP  [C402H22]  79.41 89.53 270 bottom
C791  SCD1U16V2KX-3DLGP  [C402H22]  79.41 90.42 270 bottom
C792  SCD1U16V2KX-3DLGP  [C402H22]  74.99 84.69 90 top
C793  SC1U10V2KX-1DLGP  [C402H22]  74.99 85.58 90 top
C794  SC1U10V2KX-1DLGP  [C402H22]  98.08 112.39 90 top
C795  SC1U10V2KX-1DLGP  [C402H22]  98.08 113.28 90 top
C796  SC1U10V2KX-1DLGP  [C402H22]  98.08 114.17 90 top
C797  SC4D7U6D3V3KX-DLGP  [C603H36]  98.2 115.32 90 top
C798  SC1U10V2KX-1DLGP  [C402H22]  81.34 103.38 90 bottom
C799  SC1U10V2KX-1DLGP  [C402H22]  80.6 107.72 270 bottom
C800  SC1U10V2KX-1DLGP  [C402H22]  80.86 106.83 270 bottom
C801  SC1U10V2KX-1DLGP  [C402H22]  81.36 105.41 0 bottom
C802  SC1U10V2KX-1DLGP  [C402H22]  83.45 105.18 0 bottom
C803  SC1U10V2KX-1DLGP  [C402H22]  84.34 105.18 0 bottom
C804  SC4D7U6D3V3KX-DLGP  [C603H36]  82.41 105.56 0 bottom
C805  SC1U10V2KX-1DLGP  [C402H22]  86.9 98.55 270 bottom
C806  SC1U10V2KX-1DLGP  [C402H22]  79.15 99.6 180 bottom
C807  SC1U10V2KX-1DLGP  [C402H22]  79.66 98.17 90 bottom
C808  SC1U10V2KX-1DLGP  [C402H22]  82.71 95.28 90 bottom
C809  SC1U10V2KX-1DLGP  [C402H22]  83.24 110.49 0 bottom
C810  SC4D7U6D3V3KX-DLGP  [C603H36]  80.93 110.62 0 bottom
C811  SC4D7U6D3V3KX-DLGP  [C603H36]  82.2 110.62 0 bottom
C812  SC22U6D3V3MX-1-DL-GP  [C603H40]  79.18 102.34 0 bottom
C813  SC1U10V2KX-1DLGP  [C402H22]  85.22 105.18 0 bottom
C814  SC1U10V2KX-1DLGP  [C402H22]  86.77 96.9 270 bottom
C815  SC1U10V2KX-1DLGP  [C402H22]  85.35 99.87 270 bottom
C816  SC1U10V2KX-1DLGP  [C402H22]  82.61 101.47 270 bottom
C817  SC1U10V2KX-1DLGP  [C402H22]  83.6 98.17 90 bottom
C818  SC1U10V2KX-1DLGP  [C402H22]  85.25 103.78 270 bottom
C819  SC1U10V2KX-1DLGP  [C402H22]  84.61 97.29 270 bottom
C820  SCD1U16V2KX-3DLGP  [C402H22]  83.42 99.87 90 bottom
C821  SCD1U16V2KX-3DLGP  [C402H22]  83.6 102.33 90 bottom
C822  SC22U6D3V3MX-1-DL-GP  [C603H40]  84.28 109.68 0 bottom
C823  SC1U10V2KX-1DLGP  [C402H22]  81.63 98.17 270 bottom
C824  SC1U10V2KX-1DLGP  [C402H22]  81.06 96.52 270 bottom
C825  SC1U10V2KX-1DLGP  [C402H22]  88.95 95.99 90 bottom
C826  SCD1U16V2KX-3DLGP  [C402H22]  90.76 104.42 90 bottom
C827  SC1U10V2KX-1DLGP  [C402H22]  93.2 100.13 270 bottom
C828  SC4D7U6D3V3KX-DLGP  [C603H36]  88.7 94.95 90 bottom
C829  SCD1U16V2KX-3DLGP  [C402H22]  93.2 99.27 270 bottom
C830  SC4D7U6D3V3KX-DLGP  [C603H36]  93.58 98.24 270 bottom
C835  SC1U10V2KX-1DLGP  [C402H22]  46.13 114.05 180 top
C836  SCD1U10V2KX-4GP  [C402H20]  112.55 82.93 0 top
C839  SC68P50V2JN-1GP  [C402H22]  83.88 91.93 0 bottom
C852  SC10U10V5KX-2GP  [C805H54]  81.82 115.95 270 top
C853  SCD1U16V2KX-3DLGP  [C402H22]  82.46 114.4 270 top
C859  SCD1U50V3KX-GP  [C603H36]  77.78 115.54 0 top
C864  SC1U10V2KX-1GP  [C402H22]  133.89 217.17 180 bottom
C869  SCD1U16V2KX-3DLGP  [C402H22]  43.7 114.08 0 bottom
C1491  SC1U10V2KX-1DLGP  [C402H22]  159.67 42.57 90 top
C1601  SC8P50V2DN-1DL-GP  [C402H22]  55.81 164.95 0 top
C1602  SC8P50V2DN-1DL-GP  [C402H22]  55.71 161.01 180 top
C1603  SCD1U16V2KX-3DLGP  [C402H22]  163.49 97.62 270 top
C1604  SCD1U16V2KX-3DLGP  [C402H22]  163.48 96.65 270 top
C1605  SCD1U16V2KX-3DLGP  [C402H22]  152.51 201.42 270 bottom
C1606  SCD1U16V2KX-3DLGP  [C402H22]  57.77 54.38 90 top
C1607  SC1U10V2KX-1GP  [C402H22]  90.59 129.03 90 top
C1608  SC10U6D3V3MX-DL-GP  [C603H36]  122.87 206.38 180 bottom
C1609  SC10U6D3V3MX-DL-GP  [C603H36]  122.42 222.97 270 top
C1615  SC2D2U10V3KX-1DLGP-U  [C603H36]  131.99 210.06 180 bottom
C1616  SC1U10V2KX-1GP  [C402H22]  126.78 214 0 bottom
C1617  SCD1U16V2KX-3DLGP  [C402H22]  133.26 209.93 180 bottom
C1618  SC2D7P50V2CC-GP  [C402H22]  57.61 152.43 0 top
C1619  SC2D7P50V2CC-GP  [C402H22]  57.61 154.38 180 top
C1620  SC4D7U6D3V2MX-1-GP  [C402H22]  85.44 169.78 0 bottom
C1621  SC4D7U6D3V2MX-1-GP  [C402H22]  83.37 170.13 90 bottom
C1622  SC4D7U6D3V2MX-1-GP  [C402H22]  86.6 168.38 270 bottom
C1623  SC4D7U6D3V2MX-1-GP  [C402H22]  82.25 165.27 180 bottom
C1624  SC4D7U6D3V2MX-1-GP  [C402H22]  82.71 166.88 90 bottom
C1625  SC4D7U6D3V2MX-1-GP  [C402H22]  84.66 164.39 180 bottom
C1633  SC1U10V2KX-1DLGP  [C402H22]  90.87 165.23 270 bottom
C1634  SC1U10V2KX-1DLGP  [C402H22]  87.75 164.6 180 bottom
C1635  SC1U10V2KX-1DLGP  [C402H22]  77.94 165.82 90 bottom
C1636  SC1U10V2KX-1DLGP  [C402H22]  74.72 172.6 90 bottom
C1638  SC1U10V2KX-1DLGP  [C402H22]  76.23 175.67 270 bottom
C1639  SC1U10V2KX-1DLGP  [C402H22]  73.52 178.49 0 bottom
C1640  SC1U10V2KX-1DLGP  [C402H22]  75.95 177.29 270 bottom
C1641  SC1U10V2KX-1DLGP  [C402H22]  71.52 173.03 180 bottom
C1643  SC1U10V2KX-1DLGP  [C402H22]  72.61 178.48 0 bottom
C1644  SC1U10V2KX-1DLGP  [C402H22]  57.98 178.5 0 bottom
C1645  SC1U10V2KX-1DLGP  [C402H22]  58.89 178.5 0 bottom
C1646  SC1U10V2KX-1DLGP  [C402H22]  74.41 178.48 0 bottom
C1647  SC1U10V2KX-1DLGP  [C402H22]  50.56 176.88 270 top
C1648  SC1U10V2KX-1DLGP  [C402H22]  78.76 157.72 90 bottom
C1649  SC1U10V2KX-1DLGP  [C402H22]  79.96 150.83 270 bottom
C1650  SC1U10V2KX-1DLGP  [C402H22]  79.97 149.94 270 bottom
C1651  SC1U10V2KX-1DLGP  [C402H22]  82.74 168.36 90 bottom
C1652  SC1U10V2KX-1DLGP  [C402H22]  96.86 148.79 90 top
C1653  SC1U10V2KX-1DLGP  [C402H22]  69.43 146.83 270 top
C1654  SC1U10V2KX-1DLGP  [C402H22]  69.43 145.94 270 top
C1655  SC1U10V2KX-1DLGP  [C402H22]  71.48 146.79 90 top
C1656  SC1U10V2KX-1DLGP  [C402H22]  84.41 147.24 180 bottom
C1657  SC1U10V2KX-1DLGP  [C402H22]  78.21 176.94 90 bottom
C1658  SC1U10V2KX-1DLGP  [C402H22]  78.21 176.05 90 bottom
C1659  SC1U10V2KX-1DLGP  [C402H22]  66.21 159.38 0 top
C1660  SC1U10V2KX-1DLGP  [C402H22]  76.46 152.5 180 bottom
C1661  SC1U10V2KX-1DLGP  [C402H22]  62.67 182.47 0 top
C1662  SC1U10V2KX-1DLGP  [C402H22]  72.52 152.36 90 bottom
C1663  SC1U10V2KX-1DLGP  [C402H22]  70.97 154.55 90 bottom
C1665  SC1U10V2KX-1DLGP  [C402H22]  160.97 94.31 90 top
C1666  SC1U10V2KX-1DLGP  [C402H22]  104.43 52.96 90 top
C1667  SC1U6D3V2KX-DLGP  [C402H22]  98.08 56.52 180 top
C1668  SCD1U16V2KX-3DLGP  [C402H22]  105.44 61.98 270 top
C1669  SC10U10V5KX-2GP  [C805H54]  105.19 63.5 270 top
C1670  SCD1U16V2KX-3DLGP  [C402H22]  105.53 52.07 270 top
C1671  SC10U10V5KX-2GP  [C805H54]  105.6 53.68 90 bottom
C1672  SC1KP50V2KX-1DLGP  [C402H22]  106.41 57.23 90 bottom
C1673  SC1KP50V2KX-1DLGP  [C402H22]  106.41 58.19 90 bottom
C1674  SC10U10V5KX-2DLGP  [C805H50]  27.77 6.76 0 bottom
C1696  SC1U6D3V2KX-DLGP  [C402H22]  100.69 58.83 270 top
C1698  SC1U10V2KX-1DLGP  [C402H22]  160.97 95.22 90 top
C1699  SC1U10V2KX-1DLGP  [C402H22]  104.43 53.98 90 top
C1700  SC1U6D3V2KX-DLGP  [C402H22]  160.23 92.58 0 bottom
C1701  SCD1U16V2KX-3DLGP  [C402H22]  162.06 88.77 270 top
C1702  SC10U10V5KX-2GP  [C805H54]  162.75 87.22 270 top
C1703  SCD1U16V2KX-3DLGP  [C402H22]  162.59 94.69 180 top
C1704  SC10U10V5KX-2GP  [C805H54]  166.05 91.34 0 top
C1705  SC1KP50V2KX-1DLGP  [C402H22]  170.14 89 180 top
C1706  SC1KP50V2KX-1DLGP  [C402H22]  169.2 89 180 top
C1780  SC100P50V2JN-3DLGP  [C402H22]  148.95 48.11 0 top
C1801  SC1U25V3KX-1-DLGP  [C603H36]  35.06 12.47 270 bottom
C1827  SC1U10V2KX-1GP  [C402H22]  38.64 86.49 180 bottom
C1838  SCD1U16V2KX-3DLGP  [C402H22]  90.24 118.56 180 top
C1839  SCD1U16V2KX-3DLGP  [C402H22]  88.41 118.56 180 top
C1840  SCD1U16V2KX-3DLGP  [C402H22]  89.33 118.56 180 top
C1842  SCD1U16V2KX-3DLGP  [C402H22]  87.49 118.56 180 top
C1846  SCD1U10V2KX-5GP  [C402H22]  90.61 96.95 90 bottom
C1847  SCD082U16V2KX-1-GP  [C402H22]  93.89 101.6 180 bottom
C1848  SCD68U16V3KX-3-GP  [C603H38]  101.03 100.98 0 top
C1849  SCD082U16V2KX-GP  [C402H22]  93.97 103.58 180 bottom
C1850  SCD01U25V2KX-3DLGP  [C402H22]  98.2 98.66 90 top
C1851  SCD1U16V2KX-3DLGP  [C402H22]  48.67 105.79 270 top
C1852  SCD1U16V2KX-3DLGP  [C402H22]  48.67 104.9 270 top
C1853  SCD1U16V2KX-3DLGP  [C402H22]  48.42 89.79 270 top
C1854  SCD1U16V2KX-3DLGP  [C402H22]  47.02 114.05 180 top
C1855  SCD01U50V2KX-1DLGP  [C402H22]  46.54 112.55 90 top
C1856  SCD1U16V2KX-3DLGP  [C402H22]  48.67 103.12 270 top
C1857  SCD1U16V2KX-3DLGP  [C402H22]  48.42 113.53 90 bottom
C1858  SC10U6D3V3MX-DL-GP  [C603H36]  48.47 85.72 270 top
C1859  SCD1U16V2KX-3DLGP  [C402H22]  48.45 88.52 90 bottom
C1860  SCD1U16V2KX-3DLGP  [C402H22]  47.09 96.26 0 bottom
C1861  SCD1U16V2KX-3DLGP  [C402H22]  47.79 96.14 180 top
C1864  SCD01U50V2KX-1DLGP  [C402H22]  114.5 80.38 180 top
C1867  SC1U10V2KX-1DLGP  [C402H22]  47.28 91.19 180 bottom
C1868  SCD1U16V2KX-3DLGP  [C402H22]  46.39 91.19 180 bottom
C1869  SCD1U16V2KX-3DLGP  [C402H22]  48.47 94.87 90 bottom
C1877  SC1U10V2KX-1DLGP  [C402H22]  39.3 77.04 0 bottom
C3131  SC100P3KV8JN-4-GP  [C1808H87]  65.31 19.3 0 bottom
C3452  SCD01U50V2KX-1DLGP  [C402H22]  49.44 17.78 180 top
C3455  SCD1U25V2KX-1-DL-GP  [C402H22]  35.03 24.31 180 bottom
C3456  SCD1U25V2KX-LL-GP  [C402H22]  34.78 28.09 180 top
C3457  SCD01U50V2KX-1DLGP  [C402H22]  38.51 29.84 270 bottom
C3458  SCD01U50V2KX-1DLGP  [C402H22]  37.8 29.69 180 top
C3459  SC10U25V5KX-DL-GP  [C805H58]  41.94 35.69 90 top
C3460  SC10U25V5KX-DL-GP  [C805H58]  41.94 37.97 90 top
C4101  SC1U10V2KX-1DLGP  [C402H22]  137.8 76.51 0 top
C4102  SC1U10V2KX-1DLGP  [C402H22]  145.19 70.08 270 bottom
C4202  SC1KP50V2KX-1DLGP  [C402H22]  63.53 30.73 270 bottom
C4230  SCD1U16V2KX-3GP  [C402H22]  147.56 128.83 180 top
C4254  SC10U6D3V3MX-DL-GP  [C603H36]  40.59 113.72 0 bottom
C4259  SC1U10V2KX-1DLGP  [C402H22]  156.65 123.3 180 top
C4260  SCD1U16V2KX-3GP  [C402H22]  158.96 125.32 180 top
C4261  SC10U10V5KX-2DLGP  [C805H50]  169.07 121.03 90 top
C4262  SCD1U16V2KX-3GP  [C402H22]  169.45 98.93 270 top
C4263  SC10U10V5KX-2DLGP  [C805H50]  168.69 100.46 90 top
C4265  SCD1U16V2KX-3DLGP  [C402H22]  31.53 96.9 270 bottom
C4266  SC1U10V2KX-1GP  [C402H22]  31.53 83.06 90 bottom
C4267  SCD1U16V2KX-3DLGP  [C402H22]  31.53 97.79 270 bottom
C4268  SCD1U16V2KX-3DLGP  [C402H22]  31.53 93.09 270 bottom
C4269  SCD1U16V2KX-3DLGP  [C402H22]  31.53 92.2 270 bottom
C4270  SC1KP50V2KX-1DLGP  [C402H22]  38.51 28.65 270 bottom
C4272  SCD1U16V2KX-3DLGP  [C402H22]  138.95 29.17 90 bottom
C4273  SCD1U16V2KX-3DLGP  [C402H22]  138.95 33.11 90 bottom
C4274  SCD1U16V2KX-3DLGP  [C402H22]  138.95 34 90 bottom
C4275  SCD1U16V2KX-3DLGP  [C402H22]  138.95 37.04 90 bottom
C4276  SCD1U16V2KX-3DLGP  [C402H22]  138.95 37.93 90 bottom
C4277  SCD1U16V2KX-3DLGP  [C402H22]  138.95 40.98 90 bottom
C4278  SCD1U16V2KX-3DLGP  [C402H22]  138.95 41.87 90 bottom
C4279  SCD1U16V2KX-3DLGP  [C402H22]  138.95 30.06 90 bottom
C4280  SCD1U16V2KX-3DLGP  [C402H22]  123.88 29.87 180 top
C4281  SCD01U50V2KX-1DLGP  [C402H22]  126.32 30.56 90 bottom
C4282  SCD1U16V2KX-3DLGP  [C402H22]  137.03 31 0 top
C4283  SCD1U16V2KX-3DLGP  [C402H22]  133.35 30.12 270 top
C4284  SCD01U50V2KX-1DLGP  [C402H22]  121.45 27.46 270 top
C4285  SCD01U50V2KX-1DLGP  [C402H22]  136.8 41.54 180 top
C4286  SCD01U50V2KX-1DLGP  [C402H22]  129.69 41.54 0 bottom
C4287  SCD01U50V2KX-1DLGP  [C402H22]  135.79 41.54 0 bottom
C4288  SCD1U16V2KX-3DLGP  [C402H22]  135.91 41.54 180 top
